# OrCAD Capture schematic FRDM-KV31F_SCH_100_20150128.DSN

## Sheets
1 1. Title Page: title: FRDM-KV31F; rev: X1; company: Freescale Semiconductor; note: SCH-28163 | PDF: SPF-28163; note: 6501 William Cannon Drive West; note: Austin, TX 78735-8598
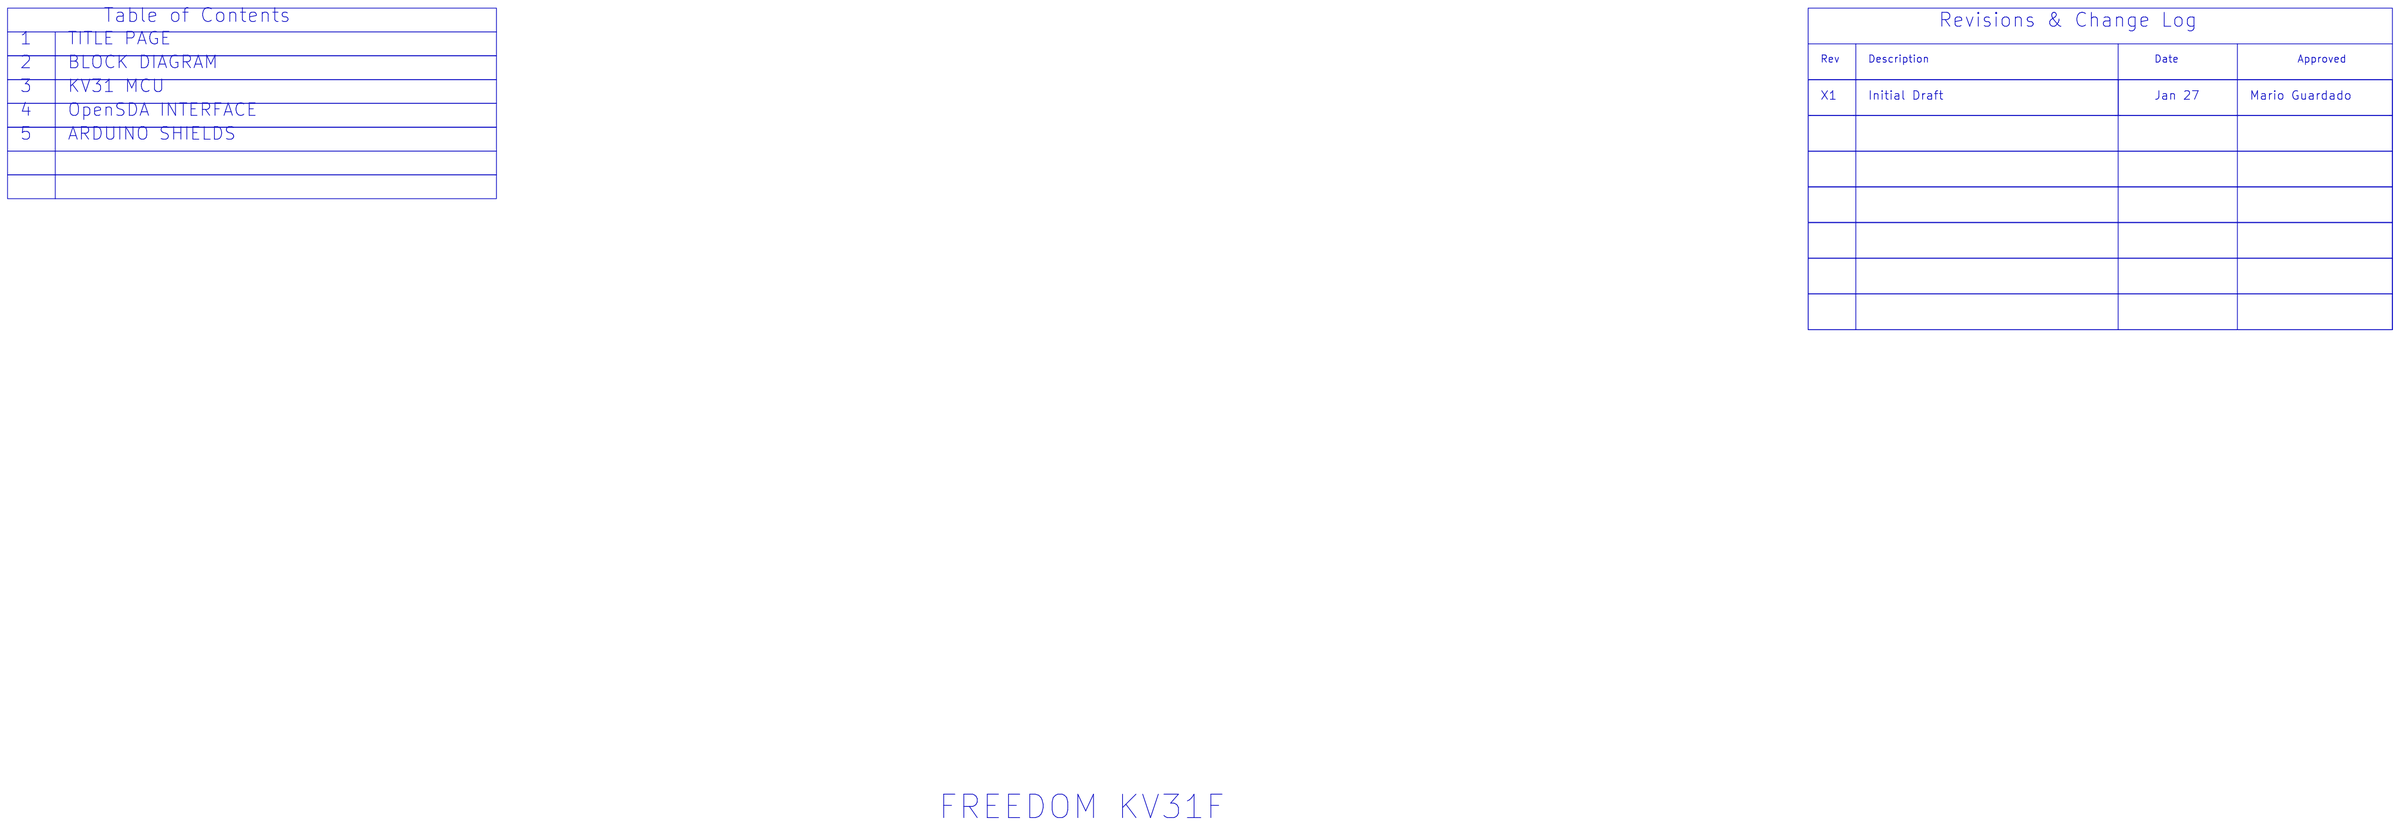
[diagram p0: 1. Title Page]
2 2. Block Diagram
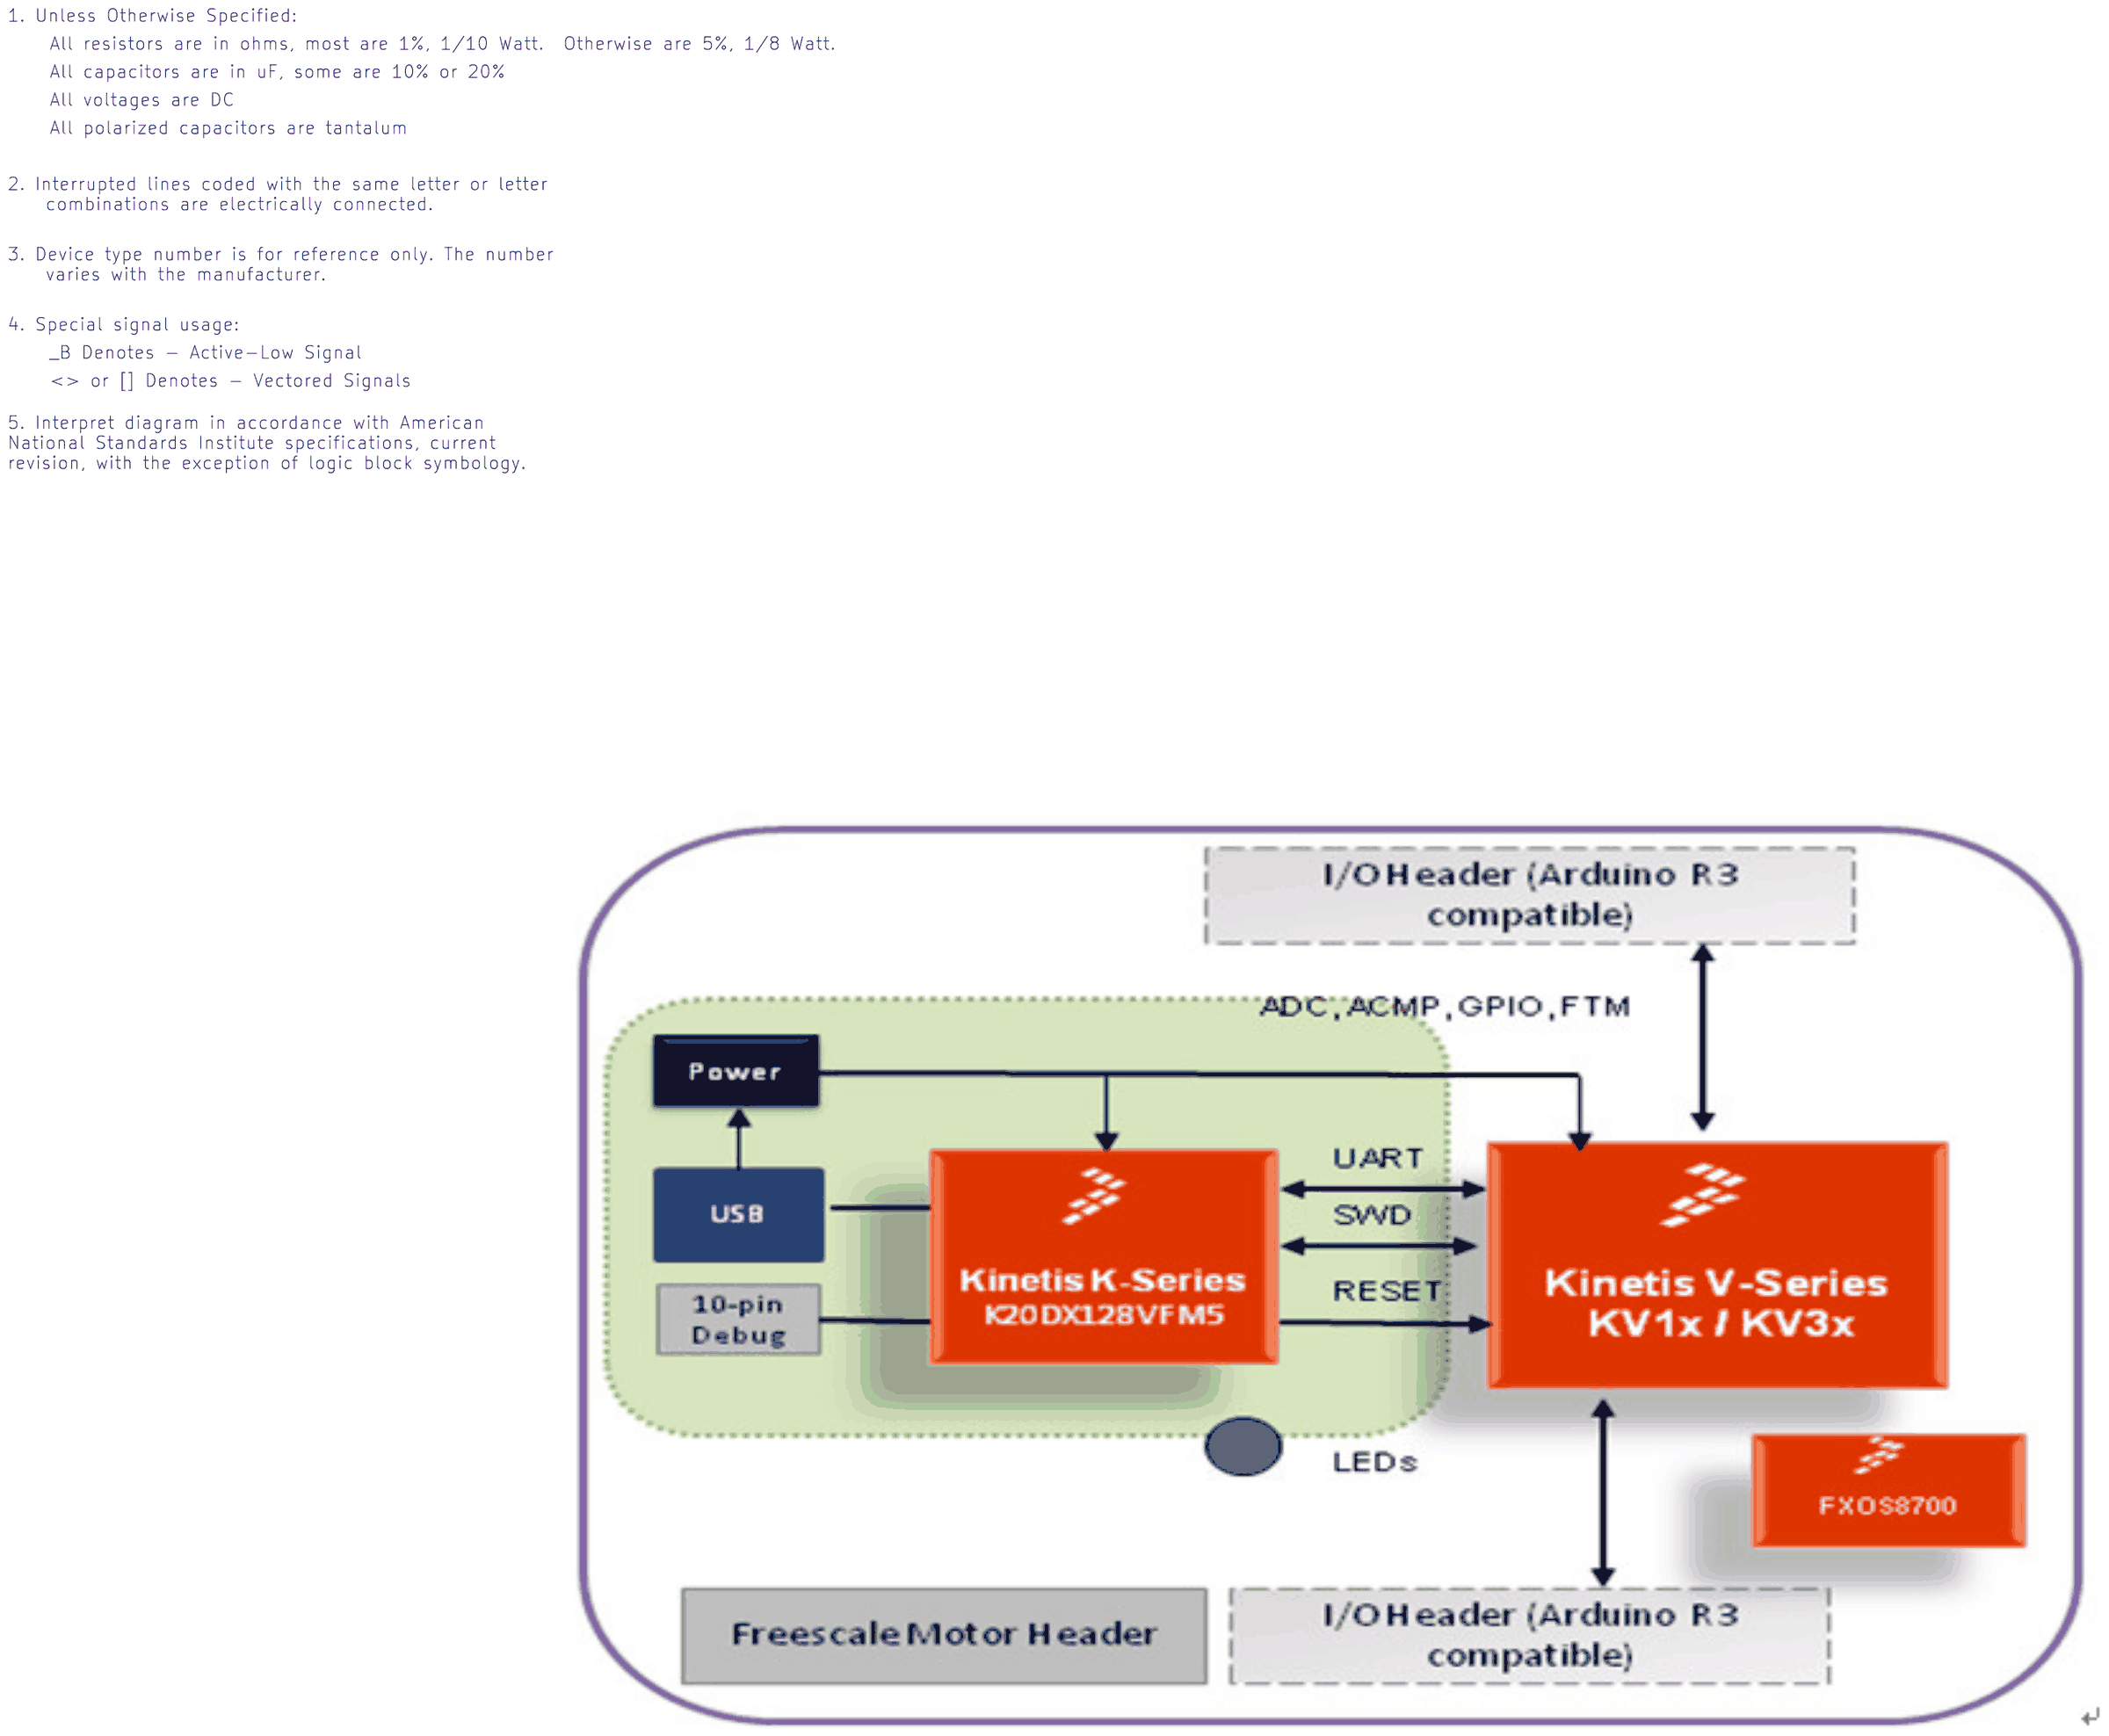
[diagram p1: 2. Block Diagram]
3 3. KV31 MCU: size C
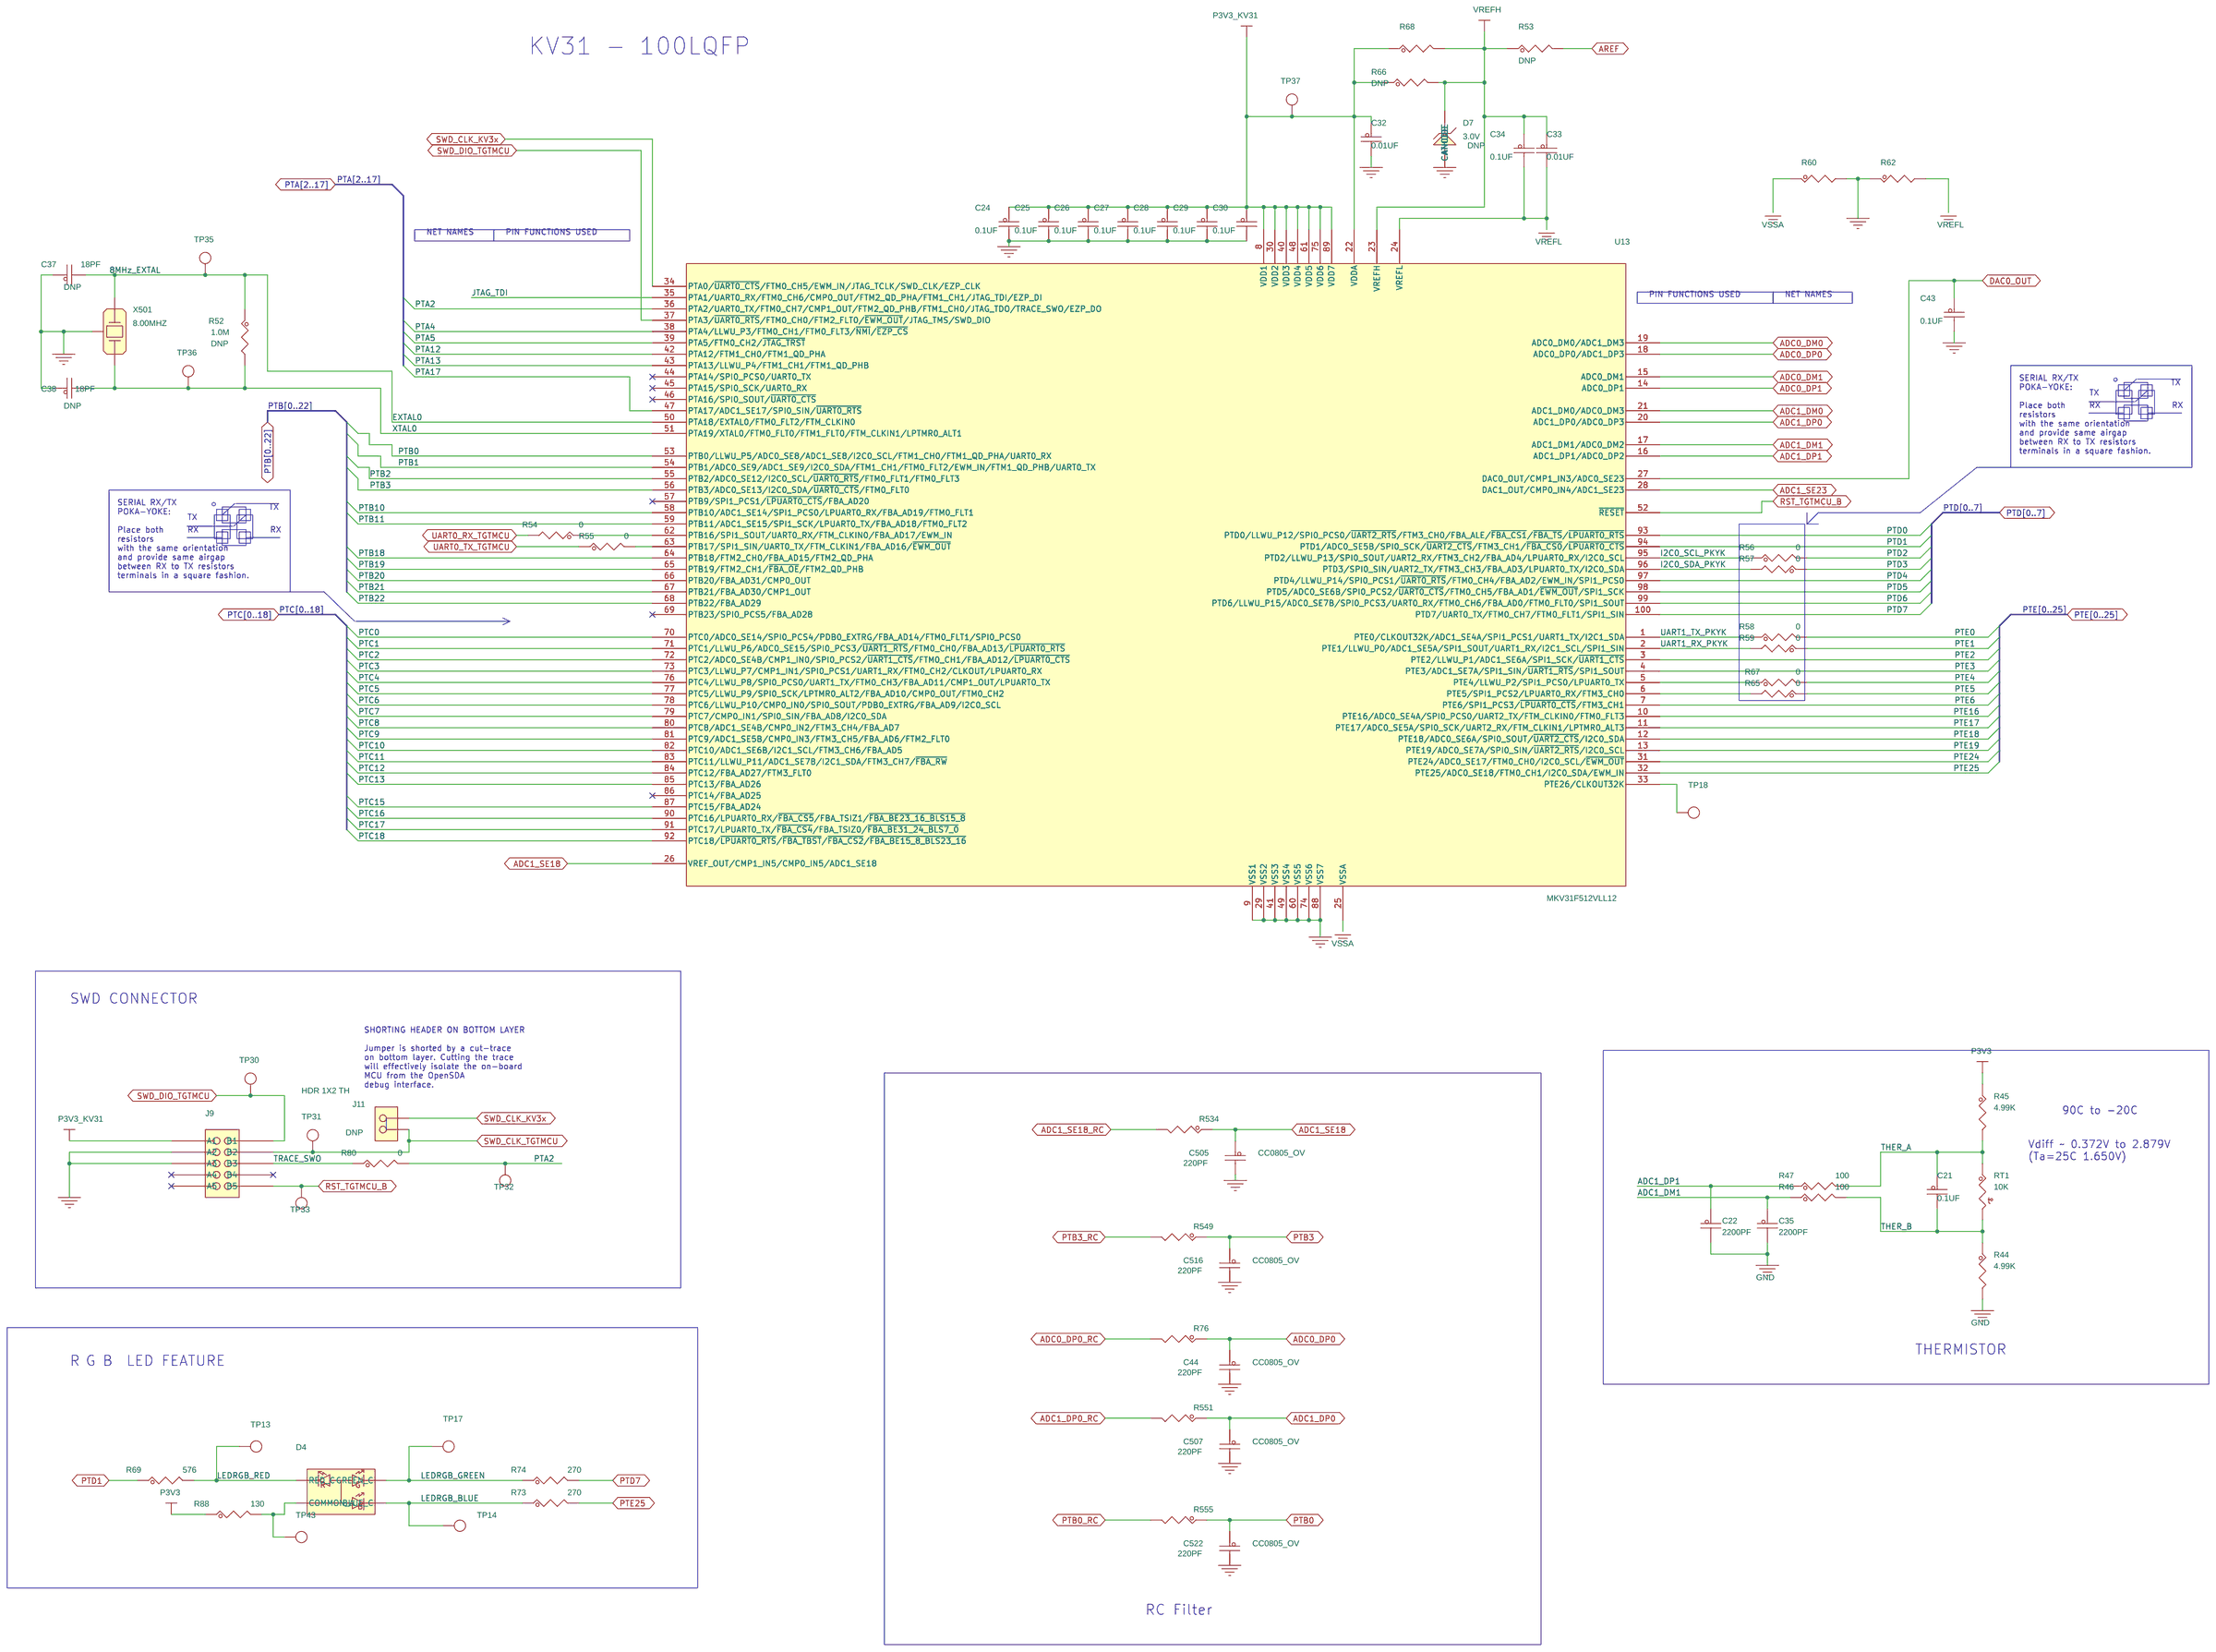
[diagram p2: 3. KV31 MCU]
4 4 OpenSDA interface: size D
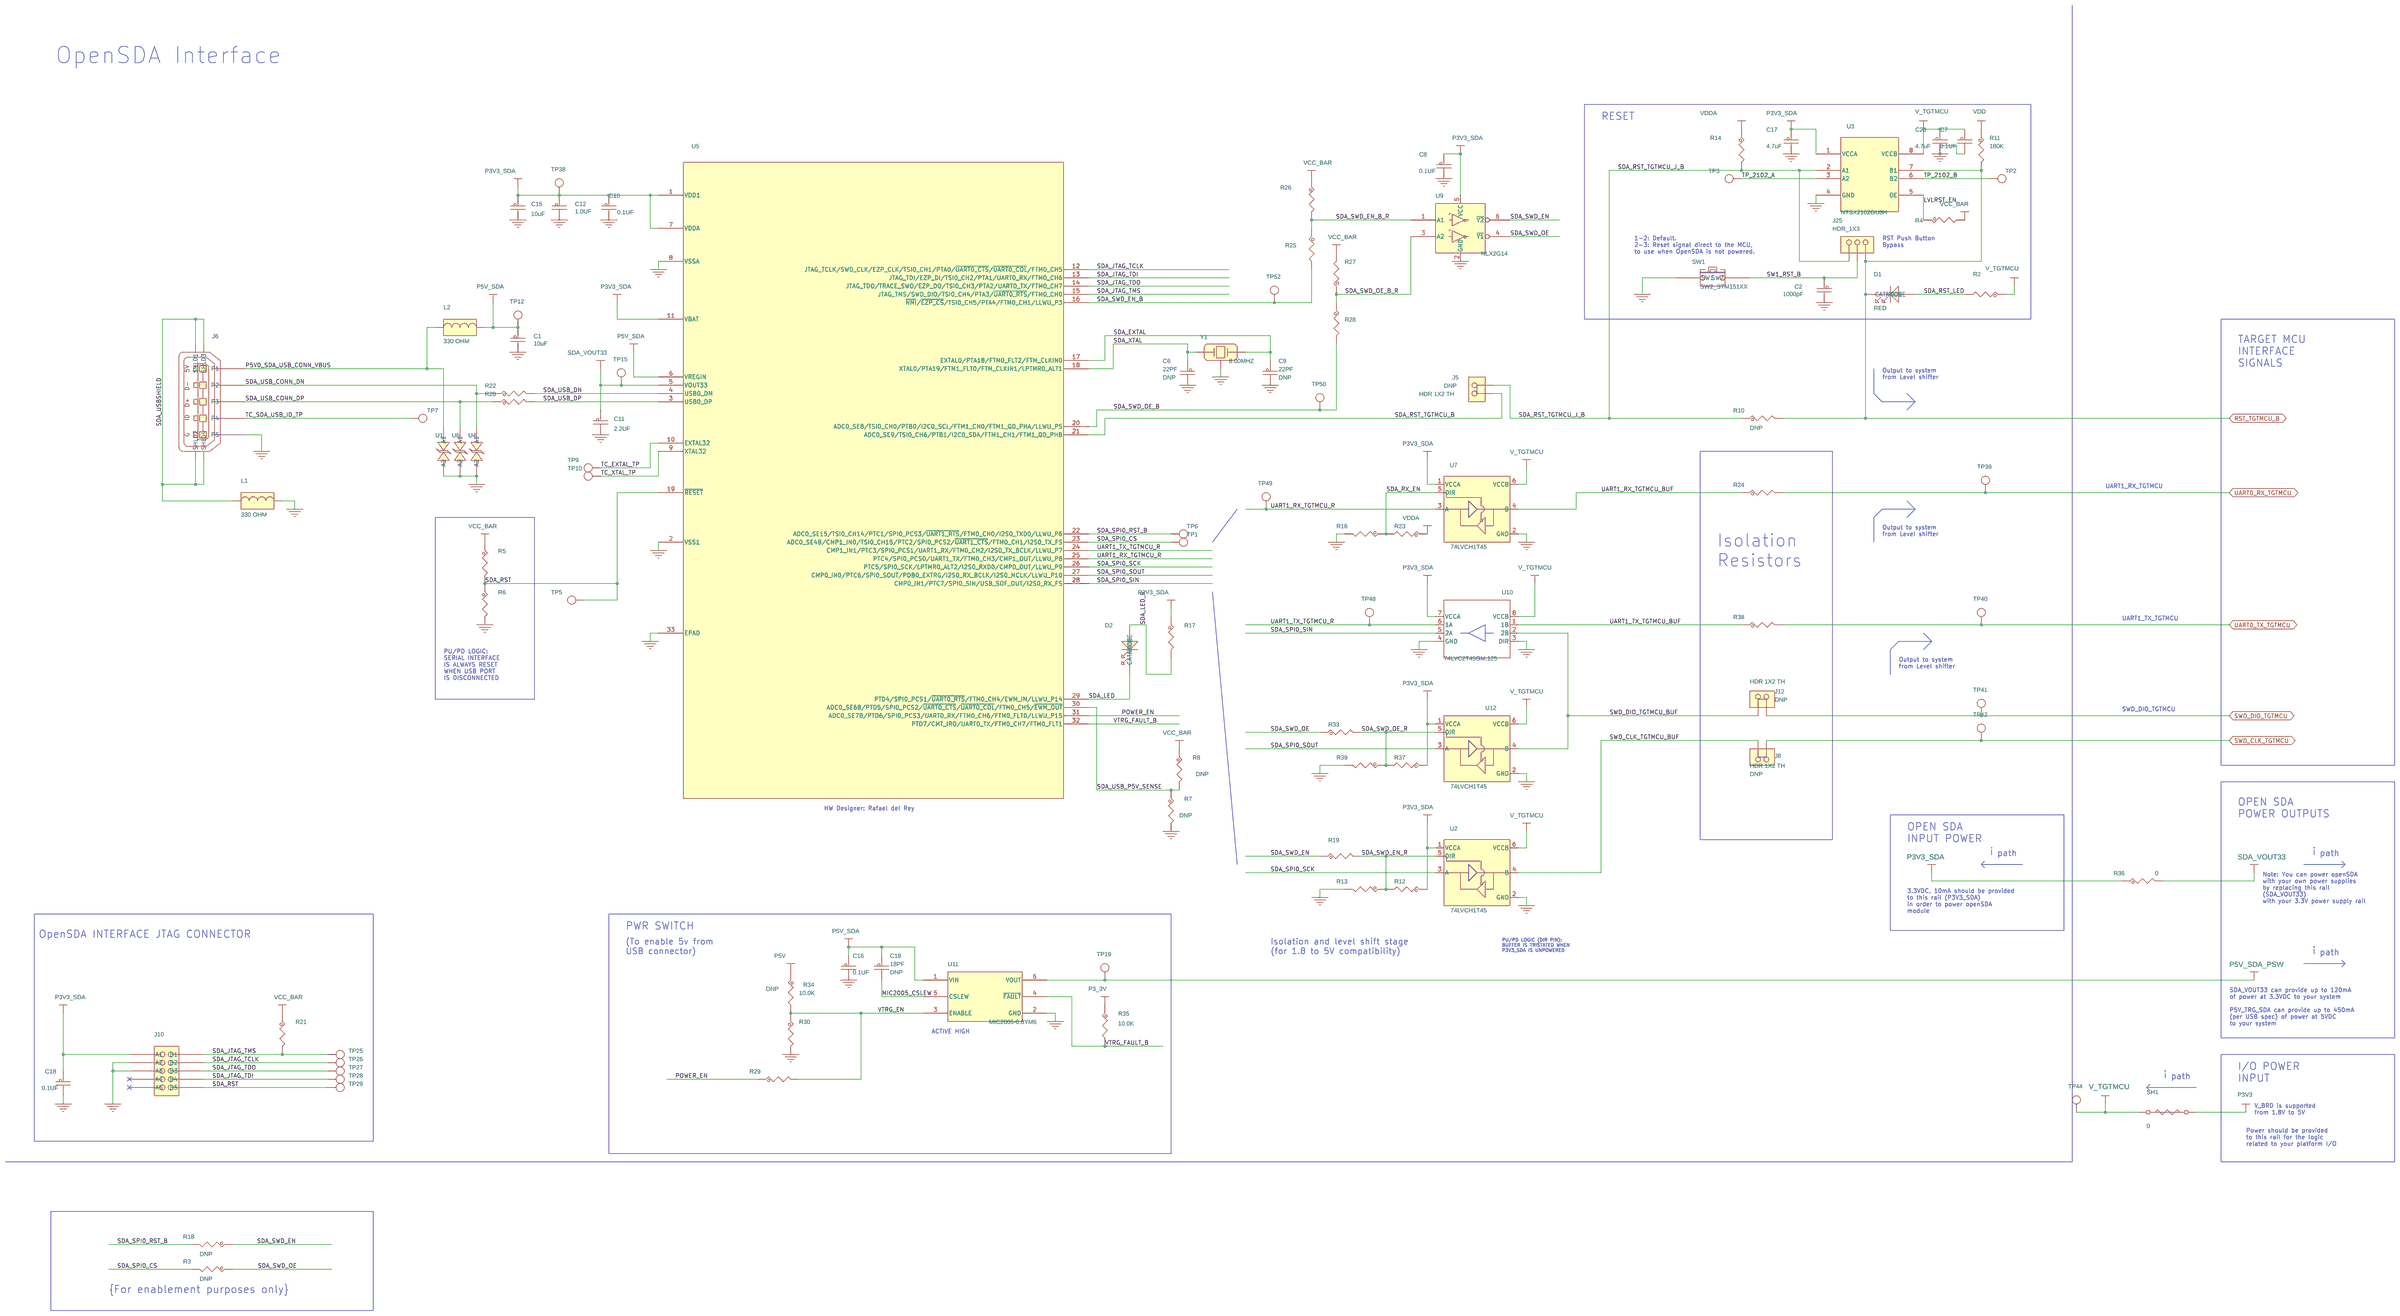
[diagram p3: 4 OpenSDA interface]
5 5. ARDUINO SHIELDS&COMBO SENSOR: size C
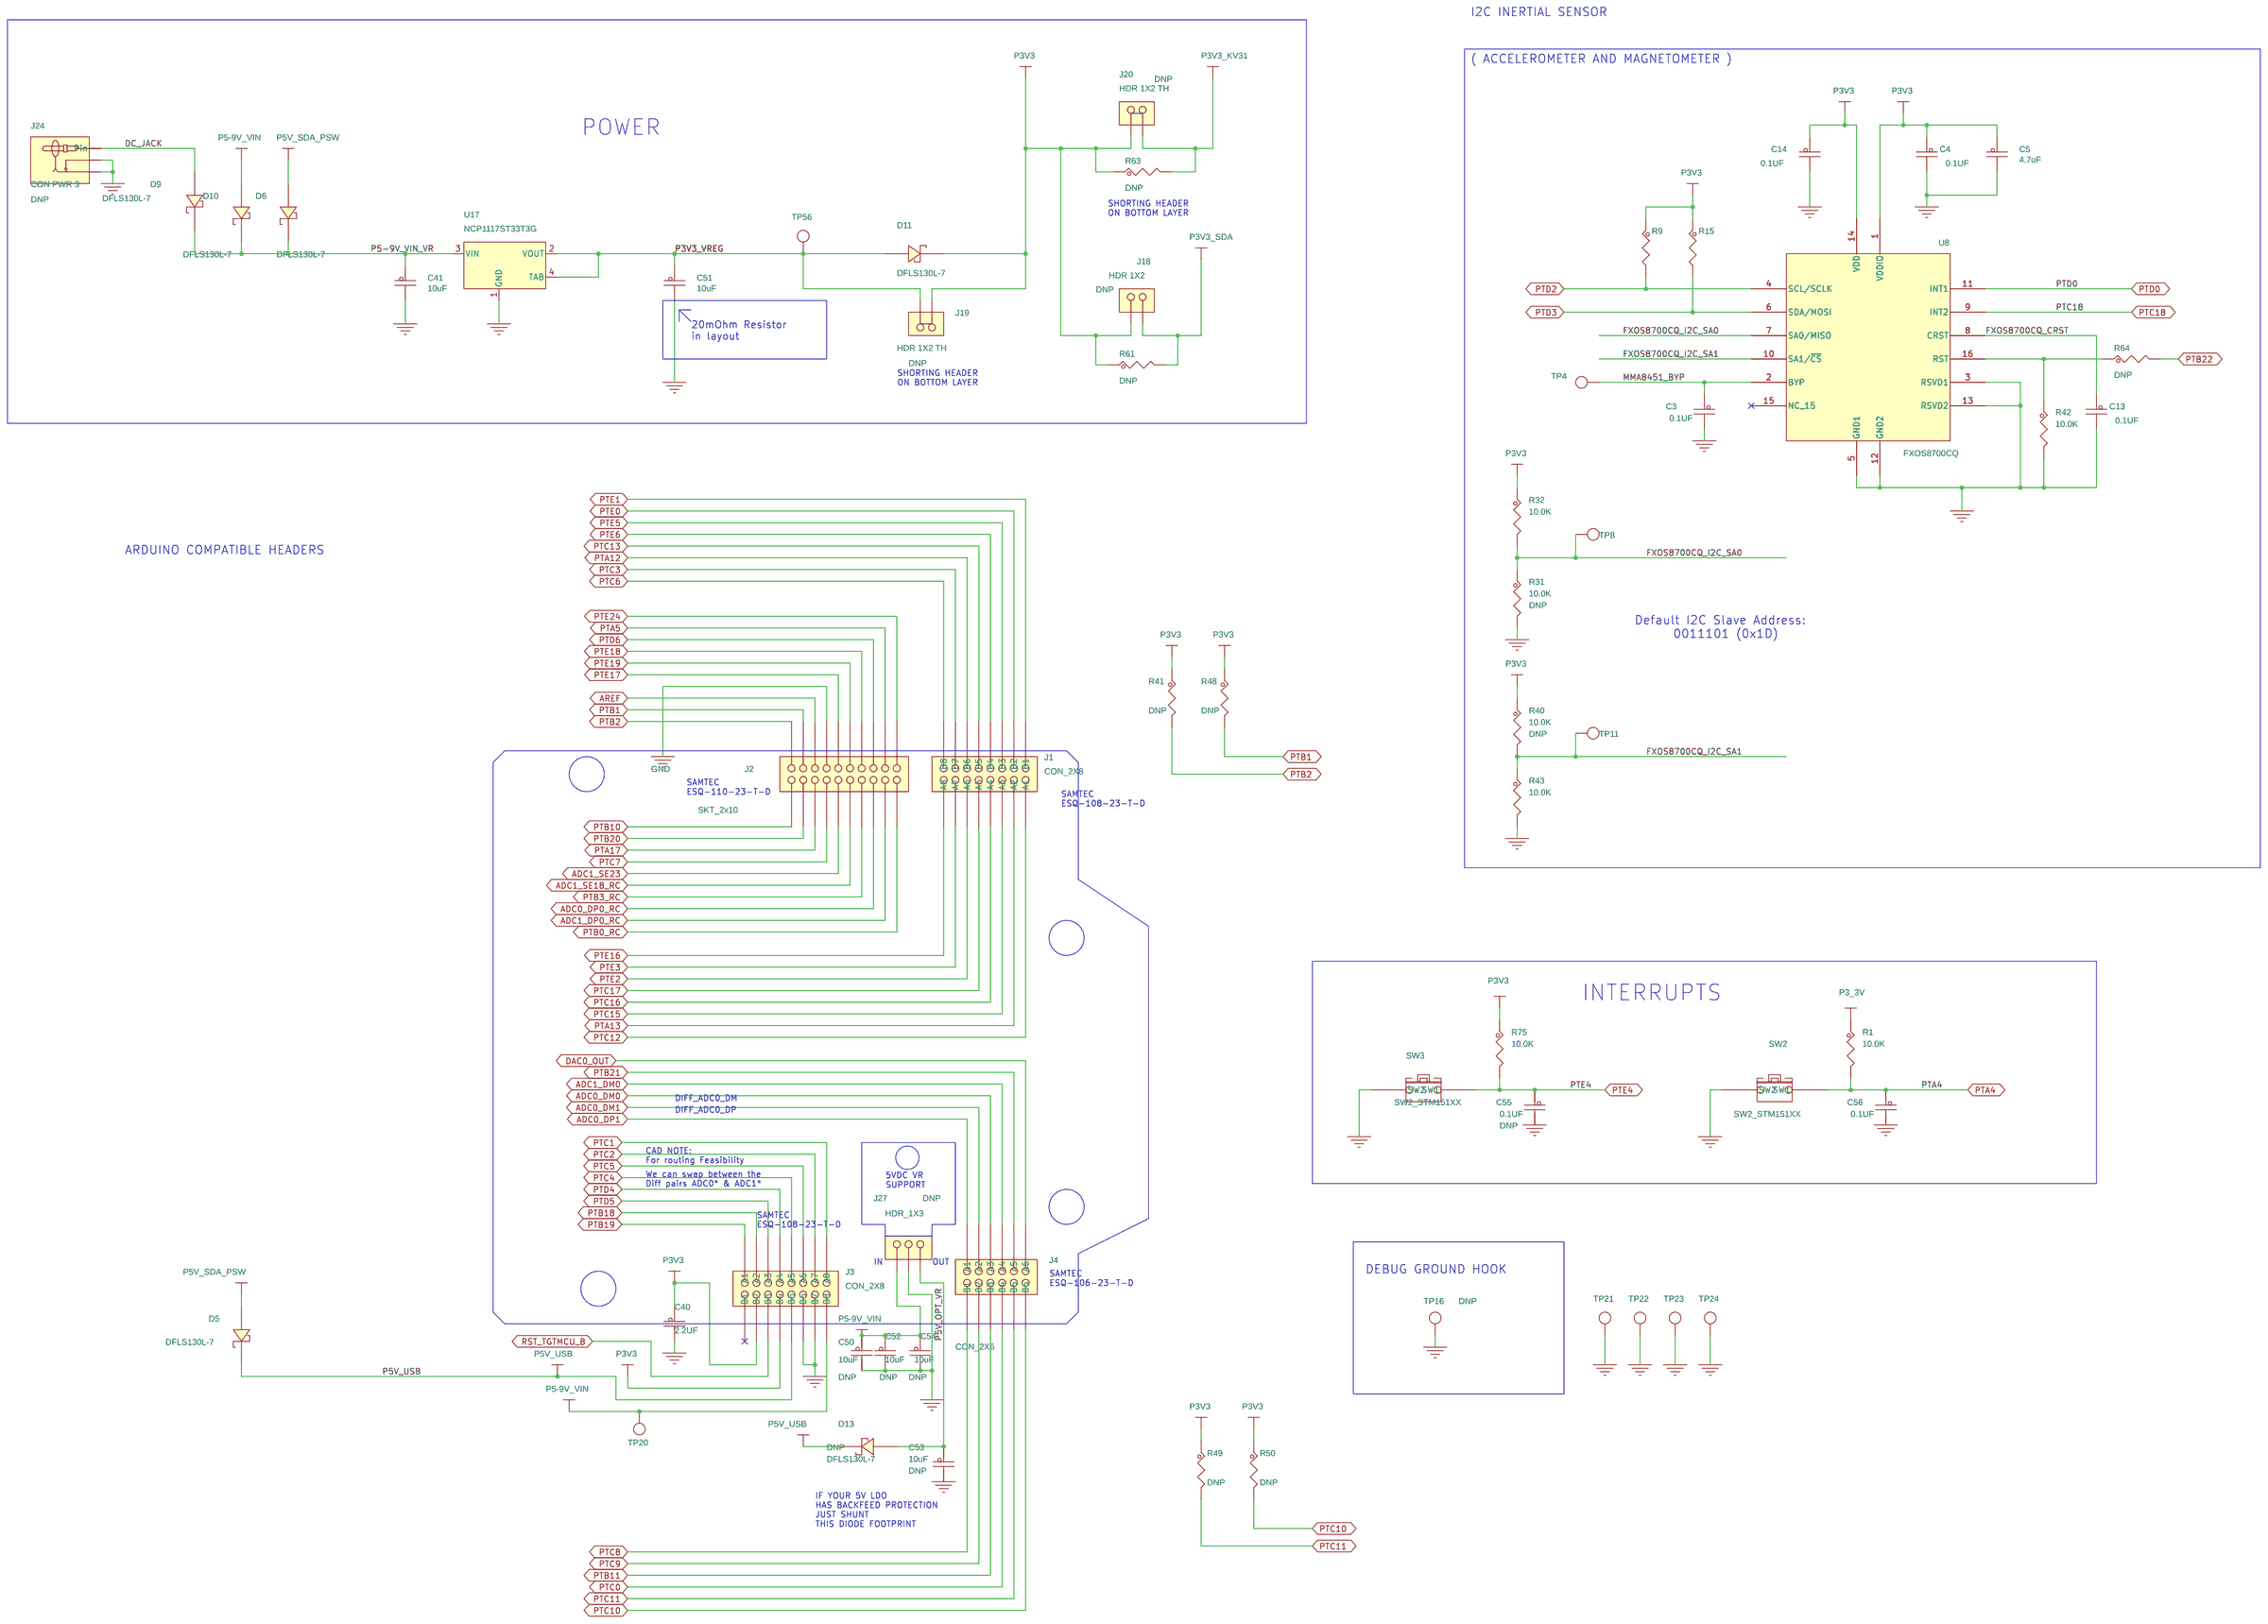
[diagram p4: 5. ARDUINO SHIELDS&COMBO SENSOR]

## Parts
sheet 3. KV31 MCU
C21  0.1UF  [CC0402_25]
C22  2200PF  [CC0402_25]
C24  0.1UF  [CC0402_25]
C25  0.1UF  [CC0402_25]
C26  0.1UF  [CC0402_25]
C27  0.1UF  [CC0402_25]
C28  0.1UF  [CC0402_25]
C29  0.1UF  [CC0402_25]
C30  0.1UF  [CC0402_25]
C32  0.01UF  [CC0402_25]
C33  0.01UF  [CC0402_25]
C34  0.1UF  [CC0402_25]
C35  2200PF  [CC0402_25]
C37  18PF  [CC0603_OV]
C38  18PF  [CC0603_OV]
C43  0.1UF  [CC0402_25]
C44  220PF  [CC0805_OV]
C505  220PF  [CC0805_OV]
C507  220PF  [CC0805_OV]
C516  220PF  [CC0805_OV]
C522  220PF  [CC0805_OV]
D4  CLV1A-FKB-CJ1M1F1BB7R4S3  [led4_3p4x3mm_smt]
D7  3.0V  [sod-323-A]
J9  HDR 2X5  [hdr_5X2_ftsh_th_nsp]
J11  HDR 1X2 TH  [SH_HDR102_BOTTOM]
R44  4.99K  [RC0603_OV]
R45  4.99K  [RC0603_OV]
R46  100  [RC0402_25]
R47  100  [RC0402_25]
R52  1.0M  [RC0603_OV]
R53  0  [RC0402_25]
R54  0  [RC0402_25]
R55  0  [RC0402_25]
R56  0  [RC0402_25]
R57  0  [RC0402_25]
R58  0  [RC0402_25]
R59  0  [RC0402_25]
R60  0  [RC0402_25]
R62  0  [RC0402_25]
R65  0  [RC0402_25]
R66  1K  [RC0603_OV]
R67  0  [RC0402_25]
R68  0  [RC0402_25]
R69  576  [RC0402_25]
R73  270  [RC0402_25]
R74  270  [RC0402_25]
R76  100  [RC0402_25]
R80  0  [RC0402_25]
R88  130  [RC0402_25]
R534  100  [RC0402_25]
R549  100  [RC0402_25]
R551  100  [RC0402_25]
R555  100  [RC0402_25]
RT1  10K  [RC0603_OV]
TP13  TPAD_030  [TPAD_030]
TP14  TPAD_030  [TPAD_030]
TP17  TPAD_030  [TPAD_030]
TP18  TPAD_030  [TPAD_030]
TP30  TPAD_030  [TPAD_030]
TP31  TPAD_030  [TPAD_030]
TP32  TPAD_030  [TPAD_030]
TP33  TPAD_030  [TPAD_030]
TP35  TPAD_030  [TPAD_030]
TP36  TPAD_030  [TPAD_030]
TP37  TPAD_030  [TPAD_030]
TP43  TPAD_030  [TPAD_030]
U13  MKV31F512VLL12  [LQFP100_0P5_14X14]
X501  8.00MHZ  [xtal3_3p35x1p45_sm]
sheet 4 OpenSDA interface
C1  10uF  [CC0402_25]
C2  1000pF  [CC0402_25]
C6  22PF  [CC0402_25]
C7  0.1UF  [CC0402_25]
C8  0.1UF  [CC0402_25]
C9  22PF  [CC0402_25]
C10  0.1UF  [CC0402_25]
C11  2.2UF  [CC0603_OV]
C12  1.0UF  [CC0402_25]
C15  10uF  [CC0603_OV]
C16  0.1UF  [CC0402_25]
C17  4.7uF  [CC0402_25]
C18  0.1UF  [CC0402_25]
C19  18PF  [CC0603_OV]
C23  4.7uF  [CC0402_25]
D1  RED  [LED_0603]
D2  LED GREEN  [LED_0603]
J5  HDR 1X2 TH  [SH_HDR102_BOTTOM]
J6  MICRO USB AB 5  [con5_microusb]
J8  HDR 1X2 TH  [SH_HDR102_BOTTOM]
J10  HDR 2X5  [hdr_5X2_ftsh_th_nsp]
J12  HDR 1X2 TH  [SH_HDR102_BOTTOM]
J25  HDR_1X3  [HDR103]
L1  330 OHM  [ind_1608]
L2  330 OHM  [ind_1608]
R2  100  [RC0402_25]
R3  0  [RC0402_25]
R4  4.7K  [RC0402_25]
R5  4.7K  [RC0402_25]
R6  10.0K  [RC0402_25]
R7  10.0K  [RC0402_25]
R8  4.7K  [RC0402_25]
R10  0  [RC0402_25]
R11  180K  [RC0402_25]
R12  4.7K  [RC0402_25]
R13  10.0K  [RC0402_25]
R14  10.0K  [RC0402_25]
R16  10.0K  [RC0402_25]
R17  220  [RC0603_OV]
R18  0  [RC0402_25]
R19  0  [RC0402_25]
R20  33  [RC0402_25]
R21  10.0K  [RC0402_25]
R22  33  [RC0402_25]
R23  4.7K  [RC0402_25]
R24  0  [RC0402_25]
R25  0  [RC0402_25]
R26  10.0K  [RC0402_25]
R27  10.0K  [RC0402_25]
R28  0  [RC0402_25]
R29  1.0K  [RC0402_25]
R30  15K  [RC0402_25]
R33  0  [RC0402_25]
R34  10.0K  [RC0402_25]
R35  10.0K  [RC0402_25]
R36  0  [RC0603_OV]
R37  4.7K  [RC0402_25]
R38  0  [RC0402_25]
R39  10.0K  [RC0402_25]
SH1  0  [SH0603]
SW1  SW2_STM151XX  [sw2_4x3mm_sm]
TP1  TPAD_030  [TPAD_030]
TP2  TPAD_030  [TPAD_030]
TP3  TPAD_030  [TPAD_030]
TP5  TPAD_030  [TPAD_030]
TP6  TPAD_030  [TPAD_030]
TP7  TPAD_030  [TPAD_030]
TP9  TPAD_030  [TPAD_030]
TP10  TPAD_030  [TPAD_030]
TP12  TPAD_030  [TPAD_030]
TP15  TPAD_030  [TPAD_030]
TP19  TPAD_030  [TPAD_030]
TP25  TPAD_030  [TPAD_030]
TP26  TPAD_030  [TPAD_030]
TP27  TPAD_030  [TPAD_030]
TP28  TPAD_030  [TPAD_030]
TP29  TPAD_030  [TPAD_030]
TP38  TPAD_030  [TPAD_030]
TP39  TPAD_030  [TPAD_030]
TP40  TPAD_030  [TPAD_030]
TP41  TPAD_030  [TPAD_030]
TP42  TPAD_030  [TPAD_030]
TP44  TPAD_030  [TPAD_030]
TP48  TPAD_030  [TPAD_030]
TP49  TPAD_030  [TPAD_030]
TP50  TPAD_030  [TPAD_030]
TP52  TPAD_030  [TPAD_030]
U1  0402ESDA-MLP  [0402_mlp]
U2  74LVCH1T45  [udfn6_1x1p5mm]
U3  NTSX2102GU8H  [xqfn8_1p45x1p25mm]
U4  0402ESDA-MLP  [0402_mlp]
U5  MK20DX128VFM5  [QFN32_S142EP]
U6  0402ESDA-MLP  [0402_mlp]
U7  74LVCH1T45  [udfn6_1x1p5mm]
U9  NLX2G14  [ullga6_1p45x1_0p5mm]
U10  74LVC2T45GM,125  [qfn8_1p6x1p6mm]
U11  MIC2005-0.8YM6  [SOT23-6_a]
U12  74LVCH1T45  [udfn6_1x1p5mm]
Y1  8.00MHZ  [xtal3_3p35x1p45_sm]
sheet 5. ARDUINO SHIELDS&COMBO SENSOR
C3  0.1UF  [CC0402_25]
C4  0.1UF  [CC0402_25]
C5  4.7uF  [CC0603_OV]
C13  0.1UF  [CC0402_25]
C14  0.1UF  [CC0402_25]
C40  2.2UF  [CC0603_OV]
C41  10uF  [CC0603_OV]
C50  10uF  [CC0603_OV]
C51  10uF  [CC0603_OV]
C52  10uF  [CC0603_OV]
C53  10uF  [CC0603_OV]
C54  10uF  [CC0603_OV]
C55  0.1UF  [CC0402_25]
C56  0.1UF  [CC0402_25]
D5  DFLS130L-7  [powerdi-123_3mmx2mm]
D6  DFLS130L-7  [powerdi-123_3mmx2mm]
D9  DFLS130L-7  [powerdi-123_3mmx2mm]
D10  DFLS130L-7  [powerdi-123_3mmx2mm]
D11  DFLS130L-7  [powerdi-123_3mmx2mm]
D13  DFLS130L-7  [powerdi-123_3mmx2mm]
J1  CON_2X8  [HDR208_ESQ_SKT]
J2  SKT_2x10  [hdr210_esq_skt]
J3  CON_2X8  [HDR208_ESQ_SKT]
J4  CON_2X6  [HDR206_ESQ_SKT]
J18  HDR 1X2  [hdr102]
J19  HDR 1X2 TH  [SH_HDR102_BOTTOM]
J20  HDR 1X2 TH  [SH_HDR102_BOTTOM]
J24  CON PWR 3  [con_jack_pj1_022_th-ra]
J27  HDR_1X3  [HDR103]
R1  10.0K  [RC0402_25]
R9  4.7K  [RC0402_25]
R15  4.7K  [RC0402_25]
R31  10.0K  [RC0402_25]
R32  10.0K  [RC0402_25]
R40  10.0K  [RC0402_25]
R41  4.7K  [RC0402_25]
R42  10.0K  [RC0402_25]
R43  10.0K  [RC0402_25]
R48  4.7K  [RC0402_25]
R49  4.7K  [RC0402_25]
R50  4.7K  [RC0402_25]
R61  0  [RC0402_25]
R63  10  [RC0402_25]
R64  0  [RC0402_25]
R75  10.0K  [RC0402_25]
SW2  SW2_STM151XX  [sw2_4x3mm_sm]
SW3  SW2_STM151XX  [sw2_4x3mm_sm]
TP4  TPAD_030  [TPAD_030]
TP8  TPAD_030  [TPAD_030]
TP11  TPAD_030  [TPAD_030]
TP16  TEST POINT WHITE  [TEST_LOOP]
TP20  TPAD_030  [TPAD_030]
TP21  TPAD_030  [TPAD_030]
TP22  TPAD_030  [TPAD_030]
TP23  TPAD_030  [TPAD_030]
TP24  TPAD_030  [TPAD_030]
TP56  TPAD_030  [TPAD_030]
U8  FXOS8700CQ  [qfn5x3_0p5_3x3]
U17  NCP1117ST33T3G  [sot223]

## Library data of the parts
C21 = CAP_NP: CAP CER 0.1UF 10V 10% X5R 0402; AGILE_PN: 150-75634; CAD_APPROVED: Yes; FPLIST: CC0402_25,CC0402_HD,0402_CC; HEIGHT: 0.64MM; MFG_NAME01: KEMET; MFG_PN01: C0402C104K8PAC; ROHS: Yes; Tolerance: 10%; VOLTAGE: 10V
C22 C35 = CAP_NP: CAP CER 2200PF 50V 10%  X7R 0402; AGILE_PN: 150-75600; CAD_APPROVED: Yes; FPLIST: CC0402_25,CC0402_HD,0402_CC; HEIGHT: 0.55MM; MFG_NAME01: MURATA; MFG_PN01: GRM155R71H222KA01D; ROHS: Yes; Tolerance: 10%; VOLTAGE: 50V
C24-C30 C34 C43 = CAP_NP: CAP CER 0.1UF 10V 10% X5R 0402; AGILE_PN: 150-75634; CAD_APPROVED: Yes; FPLIST: CC0402_25,CC0402_HD,0402_CC; HEIGHT: 0.64MM; MFG_NAME01: KEMET; MFG_PN01: C0402C104K8PAC; ROHS: Yes; TOL: 10%; Tolerance: 10%; VOLTAGE: 10V
C32 C33 = CAP_NP: CAP CER 0.01UF 16V 20% X7R 0402; AGILE_PN: 150-30082; CAD_APPROVED: Yes; FPLIST: CC0402_25,CC0402_HD,0402_CC; HEIGHT: 0.56MM; MFG_NAME01: AVX; MFG_PN01: 0402YC103MAT2A; ROHS: Yes; TOL: 20%; Tolerance: 20%; VOLTAGE: 16V
C37 C38 = CAP_NP: CAP CER 18PF 50V 5% C0G 0603; AGILE_PN: 150-75116; ASSY_OPT: DNP; CAD_APPROVED: Yes; FPLIST: CC0603_OV,CC0603,0603_CC; HEIGHT: 0.90MM; MFG_NAME01: YAGEO AMERICA; MFG_PN01: CC0603JRNPO9BN180; ROHS: Yes; TOL: 5%; Tolerance: 5%; VOLTAGE: 50V
C44 C505 C507 C516 C522 = CAP_NP: CAP CER 220PF 50V 10% X7R 0805; AGILE_PN: 150-75217; CAD_APPROVED: YES; FPLIST: CC0805_OV,CC0805,0805_CC; HEIGHT: 1.4732MM; MFG_NAME01: VENKEL COMPANY; MFG_PN01: C0805X7R500-221KNE; ROHS: Yes; Tolerance: 10%; VOLTAGE: 50V
D4 = CLV1A_LED_4P: LED RED BL GRN SGL 50/25/25mA SMT; AGILE_PN: 370-76567; CAD_APPROVED: Yes; HEIGHT: 2.1MM; MFG_NAME01: CREE, INC; ROHS: Yes
D7 = ZDIODE: DIODE ZNR -- 3V 200MW SOD323; AGILE_PN: 480-78396; ASSY_OPT: DNP; CAD_APPROVED: Yes; HEIGHT: 1.1MM; MFG_NAME01: ON SEMICONDUCTOR; MFG_PN01: MM3Z3V0T1G; ROHS: Yes
J9 J10 = CONN_HDR_5X2: HDR 2X5 TH 50MIL CTR 167H AU 91L; AGILE_PN: 210-80192; CAD_APPROVED: Yes; FPLIST: hdr_5X2_ftsh_th,hdr_5X2_ftsh_th_nsp; HEIGHT: 4.25MM; MFG_NAME01: ANYTRONIC CORPORATION LIMITED; MFG_PN01: 0922S0205011N6T-2LF; ROHS: Yes
J5 J8 J11 J12 J19 J20 = CONN_HDR_2X1: HDR 1X2 TH 100MIL SP 339H AU 98L; AGILE_PN: 210-75439; ASSY_OPT: DNP; CAD_APPROVED: YES; FPLIST: HDR102,SH_HDR102_BOTTOM; HEIGHT: 8.71 MM; MFG_NAME01: SAMTEC; MFG_PN01: TSW-102-07-G-S; PRIORITY_PN: 028-00556; ROHS: Yes
R44 R45 = RES: RES MF 4.99K 1/10W 1% 0603; AGILE_PN: 470-75771; CAD_APPROVED: Yes; FPLIST: RC0603_OV,RC0603,0603_CC; MFG_NAME01: KOA SPEER; MFG_PN01: RK73H1JTTD4991F; ROHS: Yes; Tolerance: 1%
R46 R47 = RES: RES MF 100 OHM 1/16W 1% 0402; AGILE_PN: 470-30454; CAD_APPROVED: Yes; FPLIST: RC0402_25,RC0402_HD,0402_CC; MFG_NAME01: THYE MING TECH CO LTD; MFG_PN01: CR-02FL6--100R; ROHS: Yes; Tolerance: 1%
R52 = RES: RES MF 1.0M 1/10W 5% 0603; AGILE_PN: 470-75846; ASSY_OPT: DNP; CAD_APPROVED: Yes; FPLIST: RC0603_OV,RC0603,0603_CC; HEIGHT: 0.55MM; MFG_NAME01: BOURNS; MFG_PN01: CR0603-JW-105ELF; ROHS: Yes; TOL: 5%; Tolerance: 5%
R53 R61 R63 R64 = RES: RES MF ZERO OHM 1/16W 5% 0402; AGILE_PN: 470-75394; ASSY_OPT: DNP; CAD_APPROVED: Yes; FPLIST: RC0603_OV,RC0603,R603-X2,0603_CC; MFG_NAME01: ROHM; MFG_PN01: MCR01MZPJ000; PRIORITY_PN: 006-00559; ROHS: Yes; SIGNAL_MODEL: DEFAULT_RESISTOR_0.001OHM_2_1; Tolerance: 5%; VOLTAGE: 1/16W
R54-R59 R65 R67 = RES: RES MF ZERO OHM 1/16W 5% 0402; AGILE_PN: 470-75394; CAD_APPROVED: Yes; FPLIST: RC0402_25,RC0402_HD,RC0402_X2,0402_CC; HEIGHT: 0.6MM; MFG_NAME01: ROHM; MFG_PN01: MCR01MZPJ000; ROHS: Yes; TOL: 1%; Tolerance: 5%
R19 R25 R28 R33 R60 R62 R80 = RES: RES MF ZERO OHM 1/16W 5% 0402; AGILE_PN: 470-75394; CAD_APPROVED: Yes; FPLIST: RC0402_25,RC0402_HD,RC0402_X2,0402_CC; MFG_NAME01: ROHM; MFG_PN01: MCR01MZPJ000; PRIORITY_PN: 006-00559; ROHS: Yes; SIGNAL_MODEL: DEFAULT_RESISTOR_0.001OHM_2_1; Tolerance: 5%; VOLTAGE: 1/16W
R66 = RES: RES MF 1.0K 1/10W 5% 0603; AGILE_PN: 470-75412; ASSY_OPT: DNP; CAD_APPROVED: YES; FPLIST: RC0603_OV,RC0603,0603_CC; MFG_NAME01: VENKEL COMPANY; MFG_PN01: CR0603-10W-102JT; ROHS: Yes; SIGNAL_MODEL: DEFAULT_RESISTOR_1000.000000OHM_2_1; Tolerance: 5%
R68 = RES: RES MF ZERO OHM 1/16W 5% 0402; AGILE_PN: 470-75394; CAD_APPROVED: Yes; FPLIST: RC0603_OV,RC0603,R603-X2,0603_CC; MFG_NAME01: ROHM; MFG_PN01: MCR01MZPJ000; PRIORITY_PN: 006-00559; ROHS: Yes; SIGNAL_MODEL: DEFAULT_RESISTOR_0.001OHM_2_1; Tolerance: 5%; VOLTAGE: 1/16W
R69 = RES: RES MF 576 OHM 1/16W 1% 0402; AGILE_PN: 470-30813; CAD_APPROVED: Yes; FPLIST: RC0402_25,RC0402_HD,0402_CC; MFG_NAME01: KOA SPEER; MFG_PN01: RK73H1ETTP5760F; ROHS: Yes; Tolerance: 1%
R73 R74 = RES: RES MF 270 OHM 1/16W 5% 0402; AGILE_PN: 470-30332; CAD_APPROVED: Yes; FPLIST: RC0402_25,RC0402_HD,0402_CC; MFG_NAME01: VISHAY INTERTECHNOLOGY; MFG_PN01: CRCW0402270RJNED; ROHS: Yes; Tolerance: 5%
R76 R534 R549 R551 R555 = RES: RES MF 100 OHM 1/16W 5% 0402; AGILE_PN: 470-75591; CAD_APPROVED: Yes; FPLIST: RC0402_25,RC0402_HD,RC0402_X2,0402_CC; HEIGHT: 0.55 MM; MFG_NAME01: VENKEL COMPANY; MFG_PN01: CR040216W101JT; ROHS: Yes; TOL: 1%; Tolerance: 5%
R88 = RES: RES MF 130 OHM 1/16W 1% 0402; AGILE_PN: 470-30515; CAD_APPROVED: Yes; FPLIST: RC0402_25,RC0402_HD,0402_CC; MFG_NAME01: VISHAY INTERTECHNOLOGY; MFG_PN01: CRCW0402130RFKED; ROHS: Yes; Tolerance: 1%
RT1 = THERMISTOR: THERMISTOR 10K 1/10W 1% 0603; AGILE_PN: 470-80022; CAD_APPROVED: Yes; FPLIST: RC0603_OV,RC0603,0603_CC; MFG_NAME01: MuRata; MFG_PN01: NCP18XH103F03RB; ROHS: Yes; Tolerance: 1%
TP1-TP15 TP17-TP33 TP35-TP44 TP48-TP50 TP52 TP56 = TestLoop: TEST POINT PAD 30MIL DIA SMT, NO PART TO ORDER; AGILE_PN: 211-76642; CAD_APPROVED: Yes; HEIGHT: 0.1MM; MFG_NAME01: NOTACOMPONENT; MFG_PN01: NOTACOMPONENT; ROHS: Yes
U13 = MKV10FN_LQFP_100P: IC MCU 32BIT 512KB FLASH 96KB RAM 1.71-3.6V 120MHZ LQFP100; AGILE_PN: TMP-WF-19688; CAD_APPROVED: Yes; HEIGHT: 1.7MM; MFG_NAME01: FREESCALE SEMICONDUCTOR; PRE_APN: 344-01918; ROHS: Yes
X501 = XTAL_CS: XTAL 8.00MHZ RSN CERAMIC -- SMT; AGILE_PN: 230-77664; CAD_APPROVED: Yes; HEIGHT: 0.8MM; MFG_NAME01: MURATA; MFG_PN01: CSTCE8M00G55-R0; ROHS: Yes
C1 = CAP_NP: CAP CER 10uF 10V 20% X5R 0402; AGILE_PN: 150-79255; CAD_APPROVED: Yes; FPLIST: C0402_25,CC0402_HD,0402_CC; HEIGHT: 0.7MM; MFG_NAME01: SAMSUNG; MFG_PN01: CL05A106MP5NUNC; PRIORITY_PN: 021-00242; ROHS: Yes; SIGNAL_MODEL: DEFAULT_CAPACITOR_1e+06pF_2_1; Tolerance: 20%; VOLTAGE: 10V
C2 = CAP_NP: CAP CER 1000PF 50V 5% C0G 0402; AGILE_PN: 150-76334; CAD_APPROVED: Yes; FPLIST: CC0402_25,CC0402_HD,0402_CC; HEIGHT: 0.55MM; MFG_NAME01: MURATA; MFG_PN01: GRM1555C1H102JA01D; ROHS: Yes; Tolerance: 5%; VOLTAGE: 50V
C6 C9 = CAP_NP: CAP CER 22PF 50V 5% C0G 0402; AGILE_PN: 150-75266; ASSY_OPT: DNP; CAD_APPROVED: Yes; FPLIST: CC0402_25,CC0402_HD,0402_CC; HEIGHT: 0.635MM; MFG_NAME01: AVX; MFG_PN01: 04025A220JAT2A; PRIORITY_PN: 021-00234; ROHS: Yes; SIGNAL_MODEL: DEFAULT_CAPACITOR_22.000000pF_2_1; Tolerance: 5%; VOLTAGE: 50V
C7 C8 C10 C16 C18 = CAP_NP: CAP CER 0.1UF 10V 10% X5R 0402; AGILE_PN: 150-75634; CAD_APPROVED: Yes; FPLIST: CC0402_25,CC0402_HD,0402_CC; HEIGHT: 0.64MM; MFG_NAME01: KEMET; MFG_PN01: C0402C104K8PAC; PRIORITY_PN: 021-00169; ROHS: Yes; SIGNAL_MODEL: DEFAULT_CAPACITOR_100000pF_2_1; TOL: 10%; Tolerance: 10%; VOLTAGE: 10V
C11 C40 = CAP_NP: CAP CER 2.2UF 10V 10% X7R 0603; AGILE_PN: 150-78564; CAD_APPROVED: Yes; FPLIST: CC0603_OV,CC0603,0603_CC; HEIGHT: 1.25MM; MFG_NAME01: TAIYO YUDEN; MFG_PN01: LMK107B7225KA-T; ROHS: Yes; SIGNAL_MODEL: DEFAULT_CAPACITOR_2.2e+06pF_2_1; Tolerance: 10%; VOLTAGE: 10V
C12 = CAP_NP: CAP CER 1.0UF 10V 10% X5R 0402; AGILE_PN: 150-75772; CAD_APPROVED: Yes; FPLIST: CC0402_25,CC0402_HD,0402_CC; HEIGHT: 0.6MM; MFG_NAME01: YAGEO AMERICA; MFG_PN01: CC0402KRX5R6BB105; PRIORITY_PN: 021-00242; ROHS: Yes; SIGNAL_MODEL: DEFAULT_CAPACITOR_1e+06pF_2_1; VOLTAGE: 10V
C15 = CAP_NP: CAP CER 10uF 16V 20% X5R 0603; AGILE_PN: 150-79092; CAD_APPROVED: Yes; FPLIST: CC0603_OV,CC0603,0603_CC; HEIGHT: 1mm; MFG_NAME01: TAIYO YUDEN; MFG_PN01: EMK107BBJ106MA-T; ROHS: Yes; SIGNAL_MODEL: DEFAULT_CAPACITOR_1e+07pF_2_1; TOL: 10%; Tolerance: 20%; VOLTAGE: 16V
C17 C23 = CAP_NP: CAP CER 4.7UF 6.3V 20% X5R 0402; AGILE_PN: 150-78463; CAD_APPROVED: Yes; FPLIST: CC0402_25,CC0402_HD,0402_CC; HEIGHT: 0.65MM; MFG_NAME01: VENKEL COMPANY; MFG_PN01: C0402X5R6R3-475MNP; PRIORITY_PN: 021-00169; ROHS: Yes; SIGNAL_MODEL: DEFAULT_CAPACITOR_4.7e+06pF_2_1; TOL: 10%; Tolerance: 20%; VOLTAGE: 6.3V
C19 = CAP_NP: CAP CER 18PF 50V 5% C0G 0603; AGILE_PN: 150-75116; ASSY_OPT: DNP; CAD_APPROVED: Yes; FPLIST: CC0603_OV,CC0603,0603_CC; HEIGHT: 0.90MM; MFG_NAME01: YAGEO AMERICA; MFG_PN01: CC0603JRNPO9BN180; PRIORITY_PN: 021-00320; ROHS: Yes; SIGNAL_MODEL: DEFAULT_CAPACITOR_18.000000pF_2_1; TOL: 5%; Tolerance: 5%; VOLTAGE: 50V
D1 = LED: LED ULTRA BRIGHT RED SGL 30MA 0603; AGILE_PN: 370-75079; CAD_APPROVED: Yes; HEIGHT: 0.9MM; MFG_NAME01: LITE ON; MFG_PN01: LTST-C190KRKT; ROHS: Yes
D2 = LED: LED GRN SGL 20MA 0603; AGILE_PN: 370-76565; CAD_APPROVED: Yes; HEIGHT: 0.67MM; MFG_NAME01: osram; MFG_PN01: LG L29K-G2J1-24-Z; ROHS: Yes
J6 = USB_MINI_AB_RECEPTACLE: CON 1X5 USB_MICRO_AB_RECEPTACLE RA SMT 0.65MM SP 105H AU; AGILE_PN: 211-78722; CAD_APPROVED: Yes; HEIGHT: 2.65MM; MFG_NAME01: Molex; MFG_PN01: 47589-0001; ROHS: Yes
J25 = CONN_HDR_3X1: HDR 1X3 TH 100MIL SP 330H AU 98L; AGILE_PN: 210-75442; CAD_APPROVED: Yes; HEIGHT: 8.38 MM; MFG_NAME01: SAMTEC; MFG_PN01: HTSW-103-07-S-S; PRIORITY_PN: 028-00700; ROHS: Yes
L1 L2 = BEAD: IND FER BEAD 330OHM@100MHZ 1.7A 0603; AGILE_PN: 180-78156; CAD_APPROVED: Yes; FPLIST: ind_1608,0603_CC; HEIGHT: 0.95MM; MFG_NAME01: TDK; MFG_PN01: MPZ1608S331A; PART_TYPE: FERRITE\BEAD; ROHS: Yes; Tolerance: 25%
R2 = RES: RES MF 100 OHM 1/16W 5% 0402; AGILE_PN: 470-75591; CAD_APPROVED: Yes; FPLIST: RC0402_25,RC0402_HD,RC0402_X2,0402_CC; HEIGHT: 0.55 MM; MFG_NAME01: VENKEL COMPANY; MFG_PN01: CR040216W101JT; ROHS: Yes; SIGNAL_MODEL: DEFAULT_RESISTOR_100.000000OHM_2_1; TOL: 1%; Tolerance: 5%
R3 R18 = RES: RES MF ZERO OHM 1/16W 5% 0402; AGILE_PN: 470-75394; ASSY_OPT: DNP; CAD_APPROVED: Yes; FPLIST: RC0402_25,RC0402_HD,RC0402_X2,0402_CC; MFG_NAME01: ROHM; MFG_PN01: MCR01MZPJ000; PRIORITY_PN: 006-00559; ROHS: Yes; SIGNAL_MODEL: DEFAULT_RESISTOR_0.001OHM_2_1; Tolerance: 5%; VOLTAGE: 1/16W
R4 R5 R9 R12 R15 R23 R37 = RES: RES MF 4.7K 1/16W 5% 0402; AGILE_PN: 470-75626; CAD_APPROVED: Yes; FPLIST: RC0402_25,RC0402_HD,0402_CC; HEIGHT: 0.55 MM; MFG_NAME01: YAGEO AMERICA; MFG_PN01: RC0402JR-074K7L; ROHS: Yes; SIGNAL_MODEL: DEFAULT_RESISTOR_4700OHM_2_1; TOL: 1%; Tolerance: 5%
R6 R21 R32 R42 R43 = RES: RES MF 10.0K 1/16W 1% AEC-Q200 0402; AGILE_PN: 470-75416; CAD_APPROVED: Yes; FPLIST: RC0402_25,RC0402_HD,0402_CC; MFG_NAME01: VISHAY INTERTECHNOLOGY; MFG_PN01: CRCW040210K0FKED; PRIORITY_PN: 006-00552; ROHS: Yes; SIGNAL_MODEL: DEFAULT_RESISTOR_10000OHM_2_1; Tolerance: 1%
R7 R31 R40 = RES: RES MF 10.0K 1/16W 1% AEC-Q200 0402; AGILE_PN: 470-75416; ASSY_OPT: DNP; CAD_APPROVED: Yes; FPLIST: RC0402_25,RC0402_HD,0402_CC; MFG_NAME01: VISHAY INTERTECHNOLOGY; MFG_PN01: CRCW040210K0FKED; PRIORITY_PN: 006-00552; ROHS: Yes; SIGNAL_MODEL: DEFAULT_RESISTOR_10000OHM_2_1; Tolerance: 1%
R8 R41 R48-R50 = RES: RES MF 4.7K 1/16W 5% 0402; AGILE_PN: 470-75626; ASSY_OPT: DNP; CAD_APPROVED: Yes; FPLIST: RC0402_25,RC0402_HD,0402_CC; HEIGHT: 0.55 MM; MFG_NAME01: YAGEO AMERICA; MFG_PN01: RC0402JR-074K7L; ROHS: Yes; SIGNAL_MODEL: DEFAULT_RESISTOR_4700OHM_2_1; TOL: 1%; Tolerance: 5%
R10 = RES: RES MF ZERO OHM 1/16W 5% 0402; AGILE_PN: 470-75394; ASSY_OPT: DNP; CAD_APPROVED: Yes; FPLIST: RC0402_25,RC0402_HD,RC0402_X2,0402_CC; HEIGHT: 0.45 MM; MFG_NAME01: ROHM; MFG_PN01: MCR01MZPJ000; PRIORITY_PN: 006-00559; ROHS: Yes; SIGNAL_MODEL: DEFAULT_RESISTOR_0.001OHM_2_1; TOL: 5%; Tolerance: 5%; VOLTAGE: 1/16W
R11 = RES: RES MF 180K  1/16W 1% 0402; AGILE_PN: 470-31088; CAD_APPROVED: Yes; FPLIST: RC0402_25,RC0402_HD,0402_CC; MFG_NAME01: KOA SPEER; MFG_PN01: RK73H1ETTP1803F; ROHS: Yes; SIGNAL_MODEL: DEFAULT_RESISTOR_180000OHM_2_1; Tolerance: 1%
R13 R14 R16 R26 R27 R39 = RES: RES MF 10.0K 1/16W 1% AEC-Q200 0402; AGILE_PN: 470-75416; CAD_APPROVED: Yes; FPLIST: RC0402_25,RC0402_HD,0402_CC; HEIGHT: 0.55MM; MFG_NAME01: VISHAY INTERTECHNOLOGY; MFG_PN01: CRCW040210K0FKED; PRIORITY_PN: 006-00552; ROHS: Yes; SIGNAL_MODEL: DEFAULT_RESISTOR_10000OHM_2_1; TOL: 5%; Tolerance: 1%
R17 = RES: RES MF 220 OHM 1/10W 5% 0603; AGILE_PN: 470-30297; CAD_APPROVED: Yes; FPLIST: RC0603_OV,RC0603,0603_CC; MFG_NAME01: KOA SPEER; MFG_PN01: RK73B1JTTD221J; ROHS: Yes; SIGNAL_MODEL: DEFAULT_RESISTOR_220.000000OHM_2_1; Tolerance: 5%
R20 R22 = RES: RES MF 33.0 OHM 1/16W 1% 0402; AGILE_PN: 470-75790; CAD_APPROVED: Yes; FPLIST: RC0402_25,RC0402_HD,RC0402_X2,0402_CC; MFG_NAME01: THYE MING TECH CO LTD; MFG_PN01: CR-02FL6---33R; PRIORITY_PN: 006-00556; ROHS: Yes; SIGNAL_MODEL: DEFAULT_RESISTOR_33.000000OHM_2_1; Tolerance: 1%
R24 R38 = RES: RES MF ZERO OHM 1/16W 5% 0402; AGILE_PN: 470-75394; CAD_APPROVED: Yes; FPLIST: RC0402_25,RC0402_HD,RC0402_X2,0402_CC; HEIGHT: 0.45 MM; MFG_NAME01: ROHM; MFG_PN01: MCR01MZPJ000; PRIORITY_PN: 006-00559; ROHS: Yes; SIGNAL_MODEL: DEFAULT_RESISTOR_0.001OHM_2_1; TOL: 5%; Tolerance: 5%; VOLTAGE: 1/16W
R29 = RES: RES MF 1.0K 1/16W 1% 0402; AGILE_PN: 470-76037; CAD_APPROVED: Yes; FPLIST: RC0402_25,RC0402_HD,RC0402_X2,0402_CC; HEIGHT: 0.4MM; MFG_NAME01: YAGEO AMERICA; MFG_PN01: RC0402FR-071KL; PRIORITY_PN: 006-00553; ROHS: Yes; SIGNAL_MODEL: DEFAULT_RESISTOR_1000.000000OHM_2_1; TOL: 1%; Tolerance: 1%; VOLTAGE: 1/16W
R30 = RES: RES MF 15K  1/16W 1% 0402; AGILE_PN: 470-30965; CAD_APPROVED: Yes; FPLIST: RC0402_25,RC0402_HD,0402_CC; HEIGHT: 0.4 MM; MFG_NAME01: KOA SPEER; MFG_PN01: RK73H1ETTP1502F; ROHS: Yes; SIGNAL_MODEL: DEFAULT_RESISTOR_15000OHM_2_1; TOL: 1%; Tolerance: 1%
R34 = RES: RES MF 10.0K 1/16W 1% AEC-Q200 0402; AGILE_PN: 470-75416; ASSY_OPT: DNP; CAD_APPROVED: Yes; FPLIST: RC0402_25,RC0402_HD,0402_CC; HEIGHT: 0.4MM; MFG_NAME01: VISHAY INTERTECHNOLOGY; MFG_PN01: CRCW040210K0FKED; PRIORITY_PN: 006-00552; ROHS: Yes; SIGNAL_MODEL: DEFAULT_RESISTOR_10000OHM_2_1; TOL: 1%; Tolerance: 1%
R1 R35 R75 = RES: RES MF 10.0K 1/16W 1% AEC-Q200 0402; AGILE_PN: 470-75416; CAD_APPROVED: Yes; FPLIST: RC0402_25,RC0402_HD,0402_CC; HEIGHT: 0.4MM; MFG_NAME01: VISHAY INTERTECHNOLOGY; MFG_PN01: CRCW040210K0FKED; PRIORITY_PN: 006-00552; ROHS: Yes; SIGNAL_MODEL: DEFAULT_RESISTOR_10000OHM_2_1; TOL: 1%; Tolerance: 1%
R36 = RES: RES MF ZERO OHM 1/10W -- 0603; AGILE_PN: 470-75407; CAD_APPROVED: Yes; FPLIST: RC0603_OV,RC0603,R603-X2,0603_CC; MFG_NAME01: VISHAY INTERTECHNOLOGY; MFG_PN01: CRCW06030000Z0EA; ROHS: Yes; Tolerance: 1%
SH1 = RES_SHORT-2: ZERO OHM CUT TRACE 0603 PADS; NO PART TO ORDER; AGILE_PN: 470-80018; CAD_APPROVED: Yes; FPLIST: SH0603,SH0603_CC,SH0603-X2_PIN1TO2,SH0603-X2_PIN2TO3; MFG_NAME01: LAYOUT ELEMENT ONLY; MFG_PN01: LAYOUT ELEMENT ONLY; ROHS: Yes; SIGNAL_MODEL: DEFAULT_RESISTOR_0.001OHM_2_1
SW1-SW3 = SW2_STM151XX: SW SPST MOM NO TACT 12V 50MA SMT; AGILE_PN: 510-76958; CAD_APPROVED: Yes; HEIGHT: 2MM; MFG_NAME01: E SWITCH; MFG_PN01: TL1015BF160QG; ROHS: Yes
U1 U4 U6 = DIODE_TVS_BIDIR: DIODE TVS BIDIR -- 30V 0402; AGILE_PN: 480-76179; CAD_APPROVED: Yes; HEIGHT: 0.44MM; MFG_NAME01: COOPER BUSSMANN; MFG_PN01: 0402ESDA-MLP1; PRIORITY_PN: 048-0402ESDA; ROHS: Yes
U2 U7 U12 = 74LVCH1T45_6P: IC XCVR 1BIT 3-STATE DUAL 1.2-5.5V XSON6; AGILE_PN: 312-80758; CAD_APPROVED: Yes; HEIGHT: 0.5MM; MFG_NAME01: NXP SEMICONDUCTORS; MFG_PN01: 74LVCH1T45GM,132; ROHS: Yes; VOLTAGE: 1.2-5.5V
U3 = NTSX2102GU8H_8P: IC DUAL SUPPLY XCVR 50 MBPS 5.5V XQFN8; AGILE_PN: 312-80763; CAD_APPROVED: Yes; HEIGHT: 0.5MM; MFG_NAME01: NXP Semiconductors; ROHS: Yes; VOLTAGE: 5.5V
U5 = PK20DX128V_QFN_32P: IC MCU FLASH 128KB 50MHZ 1.71-3.6V QFN32; AGILE_PN: 344-01231; CAD_APPROVED: Yes; HEIGHT: 1MM; MFG_NAME01: FREESCALE SEMICONDUCTOR; ROHS: Yes; VOLTAGE: 1.71-3.6V
U9 = NLU2GU04: IC INV DUAL SCHMITT TRIGGER 1.65-5.5V ULLGA6; AGILE_PN: 315-78830; CAD_APPROVED: Yes; HEIGHT: 0.4MM; MFG_NAME01: On Semiconductor; MFG_PN01: NLX2G14AMUTCG; ROHS: Yes; VOLTAGE: 1.65-5.5V
U10 = 74LVC2T45GM_8P: IC XCVR DUAL SUPPLY 1.2 -5.5V XQFN8; AGILE_PN: 312-80762; CAD_APPROVED: Yes; HEIGHT: 0.5MM; MFG_NAME01: NXP Semiconductors; ROHS: Yes; VOLTAGE: 5.5V
U11 = MIC2005-0.8YM6: IC LIN SW PWR 0.8A 2.5-5.5V SOT23-6; AGILE_PN: 315-79199; CAD_APPROVED: Yes; HEIGHT: 1.45MM; MFG_NAME01: MICREL; PRIORITY_PN: 051-MIC2005-08; ROHS: Yes; VOLTAGE: 2.5-5.5V
Y1 = XTAL_CS: XTAL 8.00MHZ RSN CERAMIC -- SMT; AGILE_PN: 230-77664; CAD_APPROVED: Yes; HEIGHT: 0.8MM; MFG_NAME01: MURATA; MFG_PN01: CSTCE8M00G55-R0; PRIORITY_PN: 048-00290; ROHS: Yes
C3 C4 C13 C14 C56 = CAP_NP: CAP CER 0.1UF 10V 10% X5R 0402; AGILE_PN: 150-75634; CAD_APPROVED: Yes; FPLIST: CC0402_25,CC0402_HD,0402_CC; HEIGHT: 0.64MM; MFG_NAME01: KEMET; MFG_PN01: C0402C104K8PAC; PRIORITY_PN: 021-00169; ROHS: Yes; SIGNAL_MODEL: DEFAULT_CAPACITOR_100000pF_2_1; Tolerance: 10%; VOLTAGE: 10V
C5 = CAP_NP: CAP CER 4.7uF 16V 10% X5R 0603; AGILE_PN: 150-78976; CAD_APPROVED: Yes; FPLIST: CC0603_OV,CC0603,0603_CC; HEIGHT: 0.9 MM; MFG_NAME01: TDK; MFG_PN01: C1608X5R1C475K; ROHS: Yes; SIGNAL_MODEL: DEFAULT_CAPACITOR_4.7e+06pF_2_1; Tolerance: 10%; VOLTAGE: 16V
C41 = CAP_NP: CAP CER 10uF 16V 20% X5R 0603; AGILE_PN: 150-79092; CAD_APPROVED: Yes; FPLIST: CC0603_OV,CC0603,0603_CC; HEIGHT: 1mm; MFG_NAME01: TAIYO YUDEN; MFG_PN01: EMK107BBJ106MA-T; ROHS: Yes; SIGNAL_MODEL: DEFAULT_CAPACITOR_1e+07pF_2_1; Tolerance: 20%; VOLTAGE: 16V
C50 C52 C54 = CAP_NP: CAP CER 10uF 16V 20% X5R 0603; AGILE_PN: 150-79092; ASSY_OPT: DNP; CAD_APPROVED: Yes; FPLIST: CC0603_OV,CC0603,0603_CC; HEIGHT: 1mm; MFG_NAME01: TAIYO YUDEN; MFG_PN01: EMK107BBJ106MA-T; ROHS: Yes; SIGNAL_MODEL: DEFAULT_CAPACITOR_1e+07pF_2_1; Tolerance: 20%; VOLTAGE: 16V
C51 = CAP_NP: CAP CER 10UF 10V 20% X5R 0603; AGILE_PN: 150-78609; CAD_APPROVED: Yes; FPLIST: CC0603_OV,CC0603,0603_CC; HEIGHT: 1.016MM; MFG_NAME01: TAIYO YUDEN; MFG_PN01: LMK107BJ106MALTD; ROHS: Yes; SIGNAL_MODEL: DEFAULT_CAPACITOR_1e+07pF_2_1; VOLTAGE: 10V
C53 = CAP_NP: CAP CER 10UF 10V 20% X5R 0603; AGILE_PN: 150-78609; ASSY_OPT: DNP; CAD_APPROVED: Yes; FPLIST: CC0603_OV,CC0603,0603_CC; HEIGHT: 1.016MM; MFG_NAME01: TAIYO YUDEN; MFG_PN01: LMK107BJ106MALTD; ROHS: Yes; SIGNAL_MODEL: DEFAULT_CAPACITOR_1e+07pF_2_1; VOLTAGE: 10V
C55 = CAP_NP: CAP CER 0.1UF 10V 10% X5R 0402; AGILE_PN: 150-75634; ASSY_OPT: DNP; CAD_APPROVED: Yes; FPLIST: CC0402_25,CC0402_HD,0402_CC; HEIGHT: 0.64MM; MFG_NAME01: KEMET; MFG_PN01: C0402C104K8PAC; PRIORITY_PN: 021-00169; ROHS: Yes; SIGNAL_MODEL: DEFAULT_CAPACITOR_100000pF_2_1; Tolerance: 10%; VOLTAGE: 10V
D5 D6 D9-D11 = DIODE_SCHTKY: DIODE SCH 1A 30V PowerDI123; AGILE_PN: 480-78285; CAD_APPROVED: Yes; HEIGHT: 1MM; MFG_NAME01: DIODES INC; ROHS: Yes
D13 = DIODE_SCHTKY: DIODE SCH 1A 30V PowerDI123; AGILE_PN: 480-78285; ASSY_OPT: DNP; CAD_APPROVED: Yes; HEIGHT: 1MM; MFG_NAME01: DIODES INC; ROHS: Yes
J1 J3 = CONN_HDR_8X2: CON 2X8 SKT TH 100MIL CTR 545H SN 190L; AGILE_PN: 210-80538; CAD_APPROVED: Yes; HEIGHT: 13.843MM; MFG_NAME01: samtec; MFG_PN01: ESQ-108-23-T-D; ROHS: Yes
J2 = CONN_HDR_10X2: CON 2X10 SKT TH 100MIL CTR 540H SN 190L; AGILE_PN: 210-80537; CAD_APPROVED: Yes; HEIGHT: 13.72MM; MFG_NAME01: SAMTEC; MFG_PN01: ESQ-110-23-T-D; ROHS: Yes
J4 = CONN_HDR_6X2: CON 2X6 SKT TH 100MIL CTR 540H SN 190L; AGILE_PN: 210-80536; CAD_APPROVED: Yes; HEIGHT: 13.72MM; MFG_NAME01: SAMTEC; MFG_PN01: ESQ-106-23-T-D; ROHS: Yes
J18 = CONN_HDR_2X1: HDR 1X2 TH 100MIL SP 330H SN 115L; AGILE_PN: 210-76752; ASSY_OPT: DNP; CAD_APPROVED: Yes; HEIGHT: 8.58MM; MFG_NAME01: Samtec; MFG_PN01: TSW-102-23-T-S; ROHS: Yes
J24 = DC_POWER_JACK: CON 3 PWR JACK RA TH --- 201H AG 118L; AGILE_PN: 210-80316; ASSY_OPT: DNP; CAD_APPROVED: Yes; HEIGHT: 5.1MM; MFG_NAME01: CUI Inc; MFG_PN01: PJ1-022; ROHS: Yes
J27 = CONN_HDR_3X1: HDR 1X3 TH 100MIL SP 330H AU 98L; AGILE_PN: 210-75442; ASSY_OPT: DNP; CAD_APPROVED: Yes; HEIGHT: 8.38 MM; MFG_NAME01: SAMTEC; MFG_PN01: HTSW-103-07-S-S; PRIORITY_PN: 028-00700; ROHS: Yes
TP16 = TestLoop: TEST POINT WHITE 40 MIL DRILL 180 MIL TH 109L; AGILE_PN: 210-75685; ASSY_OPT: DNP; CAD_APPROVED: Yes; HEIGHT: 4.8 MM; MFG_NAME01: KEYSTONE ELECTRONICS; MFG_PN01: 5002; PRIORITY_PN: 028-00434; ROHS: Yes
U8 = FXOS8700CQ_QFN_16P: IC ACCELEROMETER AND MAGNETOMETER SENSOR 3-AXIS 2.5V QFN16; AGILE_PN: TMP-WF-16648; CAD_APPROVED: Yes; HEIGHT: 1.25MM; MFG_NAME01: Freescale Semiconductor; PRE_APN: 312-80418; ROHS: Yes; VOLTAGE: 2.5V
U17 = LD1117AS18: IC VREG LDO 1A 3.3V SOT223; AGILE_PN: 312-80039; CAD_APPROVED: Yes; HEIGHT: 1.8MM; MFG_NAME01: ON Semiconductor; ROHS: Yes

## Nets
GND: C1.2 C2.2 C3.2 C4.2 C5.2 C6.2 C7.2 C8.2 C9.2 C10.2 C11.2 C12.2 C13.2 C14.2 C15.2 C16.2 C17.2 C18.2 C22.2 C23.2 C24.2 C25.2 C26.2 C27.2 C28.2 C29.2 C30.2 C32.2 C35.2 C37.1 C38.1 C40.2 C41.2 C43.2 C44.2 C50.2 C51.2 C52.2 C53.2 C54.2 C55.2 C56.2 C505.2 C507.2 C516.2 C522.2 D7.A(ANODE) J2.14 J3.12(B6) J3.14(B7) J6.5(P5) J9.3(A2) J9.5(A3) J10.3(A2) J10.5(A3) J24.2 J24.3 J27.2 L1.2 R6.2 R7.2 R13.2 R16.2 R30.2 R31.2 R39.2 R42.2 R43.2 R44.2 R60.2 R62.1 SW1.1(SW1) SW2.2(SW2) SW3.2(SW2) TP16.1(Pin1) TP21.1(Pin1) TP22.1(Pin1) TP23.1(Pin1) TP24.1(Pin1) U1.2(A2) U2.2(GND) U3.4(GND) U4.2(A2) U5.2(VSS1) U5.8(VSSA) U5.33(EPAD) U6.2(A2) U7.2(GND) U8.3(RSVD1) U8.5(GND1) U8.12(GND2) U8.13(RSVD2) U9.2(GND) U10.3(DIR) U10.4(GND) U11.2(GND) U12.2(GND) U13.9(VSS1) U13.29(VSS2) U13.41(VSS3) U13.49(VSS4) U13.60(VSS5) U13.74(VSS6) U13.88(VSS7) U17.1(GND) X501.2 Y1.2
P3V3: C4.1 C5.1 C14.1 C40.1 D11.C J3.4(B2) J3.8(B4) J18.2 J19.1 J20.1 R1.1 R9.1 R15.1 R32.1 R40.1 R41.1 R45.1 R48.1 R49.1 R50.1 R61.1 R63.1 R75.1 R88.1 SH1.2 U8.1(VDDIO) U8.14(VDD)
P3V3_KV31: C24.1 C25.1 C26.1 C27.1 C28.1 C29.1 C30.1 C32.1 J9.1(A1) J20.2 R63.2 R66.1 R68.1 TP37.1(Pin1) U13.8(VDD1) U13.22(VDDA) U13.30(VDD2) U13.40(VDD3) U13.48(VDD4) U13.61(VDD5) U13.75(VDD6) U13.89(VDD7)
P3V3_SDA: C8.1 C10.1 C12.1 C15.1 C17.1 C18.1 J10.1(A1) J18.1 R4.2 R12.1 R14.1 R17.1 R21.1 R23.1 R26.1 R27.2 R35.1 R36.1 R37.1 R61.2 TP38.1(Pin1) U2.1(VCCA) U3.1(VCCA) U5.1(VDD1) U5.7(VDDA) U5.11(VBAT) U7.1(VCCA) U9.5(VCC) U10.7(VCCA) U12.1(VCCA)
P3V3_VREG: C51.1 D11.A J19.2 TP56.1(Pin1) U17.2(VOUT) U17.4(TAB)
P5V0_SDA_USB_CONN_VBUS: J6.1(P1) L2.1 U1.1(A1)
P5V_OPT_VR: C53.1 D13.A J27.3
P5V_SDA: C1.1 C16.1 C19.1 L2.2 R5.1 R8.1 R34.1 TP12.1(Pin1) U5.6(VREGIN) U11.1(VIN)
P5V_SDA_PSW: D5.A D6.A TP19.1(Pin1) U11.6(VOUT)
P5V_USB: D5.C D13.C J3.10(B5)
VSSA: R60.1 U13.25(VSSA)
8MHz_EXTAL: C37.2 R52.1 TP35.1(Pin1) U13.50(PTA18/EXTAL0/FTM0_FLT2/FTM_CLKIN0) X501.1
ADC0_DM0: J4.5(A3) U13.19(ADC0_DM0/ADC1_DM3)
ADC0_DM1: J4.3(A2) U13.15(ADC0_DM1)
ADC0_DP0: C44.1 R76.1 U13.18(ADC0_DP0/ADC1_DP3)
ADC0_DP0_RC: J2.5 R76.2
ADC0_DP1: J4.1(A1) U13.14(ADC0_DP1)
ADC1_DM0: J4.7(A4) U13.21(ADC1_DM0/ADC0_DM3)
ADC1_DM1: C35.1 R46.1 U13.17(ADC1_DM1/ADC0_DM2)
ADC1_DP0: C507.1 R551.1 U13.20(ADC1_DP0/ADC0_DP3)
ADC1_DP0_RC: J2.3 R551.2
ADC1_DP1: C22.1 R47.1 U13.16(ADC1_DP1/ADC0_DP2)
ADC1_SE18: C505.1 R534.1 U13.26(VREF_OUT/CMP1_IN5/CMP0_IN5/ADC1_SE18)
ADC1_SE18_RC: J2.9 R534.2
ADC1_SE23: J2.11 U13.28(DAC1_OUT/CMP0_IN4/ADC1_SE23)
AREF: J2.16 R53.2
DAC0_OUT: C43.1 J4.11(A6) U13.27(DAC0_OUT/CMP1_IN3/ADC0_SE23)
DC_JACK: D9.A J24.1(Pin)
FXOS8700CQ_CRST: C13.1 U8.8(CRST)
FXOS8700CQ_I2C_SA0: R31.1 R32.2 TP8.1(Pin1) U8.7(SA0/MISO)
FXOS8700CQ_I2C_SA1: R40.2 R43.1 TP11.1(Pin1) U8.10(SA1/~{CS})
I2C0_SCL_PKYK: R56.1 U13.95(PTD2/LLWU_P13/SPI0_SOUT/UART2_RX/FTM3_CH2/FBA_AD4/LPUART0_RX/I2C0_SCL)
I2C0_SDA_PKYK: R57.2 U13.96(PTD3/SPI0_SIN/UART2_TX/FTM3_CH3/FBA_AD3/LPUART0_TX/I2C0_SDA)
JTAG_TDI: U13.35(PTA1/UART0_RX/FTM0_CH6/CMP0_OUT/FTM2_QD_PHA/FTM1_CH1/JTAG_TDI/EZP_DI)
LEDRGB_BLUE: D4.3(BLUE_C) R73.1 TP14.1(Pin1)
LEDRGB_GREEN: D4.4(GREEN_C) R74.1 TP17.1(Pin1)
LEDRGB_RED: D4.1(RED_C) R69.2 TP13.1(Pin1)
LVLRST_EN: R4.1 U3.5(OE)
MIC2005_CSLEW: C19.2 U11.5(CSLEW)
MMA8451_BYP: C3.1 TP4.1(Pin1) U8.2(BYP)
P5-9V_VIN: C50.1 C52.1 C54.1 D10.A J3.16(B8) J27.1 TP20.1(Pin1)
P5-9V_VIN_VR: C41.1 D6.C D9.C D10.C U17.3(VIN)
POWER_EN: R29.1 U5.31(ADC0_SE7B/PTD6/SPI0_PCS3/UART0_RX/FTM0_CH6/FTM0_FLT0/LLWU_P15)
PTA2: R80.2 TP32.1(Pin1) U13.36(PTA2/UART0_TX/FTM0_CH7/CMP1_OUT/FTM2_QD_PHB/FTM1_CH0/JTAG_TDO/TRACE_SWO/EZP_DO)
PTA4: C56.1 R1.2 SW2.1(SW1) U13.38(PTA4/LLWU_P3/FTM0_CH1/FTM0_FLT3/~{NMI}/~{EZP_CS})
PTA5: J2.4 U13.39(PTA5/FTM0_CH2/~{JTAG_TRST})
PTA12: J1.12(B6) U13.42(PTA12/FTM1_CH0/FTM1_QD_PHA)
PTA13: J1.3(A2) U13.43(PTA13/LLWU_P4/FTM1_CH1/FTM1_QD_PHB)
PTA17: J2.15 U13.47(PTA17/ADC1_SE17/SPI0_SIN/~{UART0_RTS})
PTB0: C522.1 R555.1 U13.53(PTB0/LLWU_P5/ADC0_SE8/ADC1_SE8/I2C0_SCL/FTM1_CH0/FTM1_QD_PHA/UART0_RX)
PTB0_RC: J2.1 R555.2
PTB1: J2.18 R48.2 U13.54(PTB1/ADC0_SE9/ADC1_SE9/I2C0_SDA/FTM1_CH1/FTM0_FLT2/EWM_IN/FTM1_QD_PHB/UART0_TX)
PTB2: J2.20 R41.2 U13.55(PTB2/ADC0_SE12/I2C0_SCL/~{UART0_RTS}/FTM0_FLT1/FTM0_FLT3)
PTB3: C516.1 R549.1 U13.56(PTB3/ADC0_SE13/I2C0_SDA/~{UART0_CTS}/FTM0_FLT0)
PTB3_RC: J2.7 R549.2
PTB10: J2.19 U13.58(PTB10/ADC1_SE14/SPI1_PCS0/LPUART0_RX/FBA_AD19/FTM0_FLT1)
PTB11: J4.6(B3) U13.59(PTB11/ADC1_SE15/SPI1_SCK/LPUART0_TX/FBA_AD18/FTM0_FLT2)
PTB18: J3.3(A2) U13.64(PTB18/FTM2_CH0/FBA_AD15/FTM2_QD_PHA)
PTB19: J3.1(A1) U13.65(PTB19/FTM2_CH1/~{FBA_OE}/FTM2_QD_PHB)
PTB20: J2.17 U13.66(PTB20/FBA_AD31/CMP0_OUT)
PTB21: J4.9(A5) U13.67(PTB21/FBA_AD30/CMP1_OUT)
PTB22: R64.2 U13.68(PTB22/FBA_AD29)
PTC0: J4.8(B4) U13.70(PTC0/ADC0_SE14/SPI0_PCS4/PDB0_EXTRG/FBA_AD14/FTM0_FLT1/SPI0_PCS0)
PTC1: J3.15(A8) U13.71(PTC1/LLWU_P6/ADC0_SE15/SPI0_PCS3/~{UART1_RTS}/FTM0_CH0/FBA_AD13/~{LPUART0_RTS})
PTC2: J3.13(A7) U13.72(PTC2/ADC0_SE4B/CMP1_IN0/SPI0_PCS2/~{UART1_CTS}/FTM0_CH1/FBA_AD12/~{LPUART0_CTS})
PTC3: J1.14(B7) U13.73(PTC3/LLWU_P7/CMP1_IN1/SPI0_PCS1/UART1_RX/FTM0_CH2/CLKOUT/LPUART0_RX)
PTC4: J3.9(A5) U13.76(PTC4/LLWU_P8/SPI0_PCS0/UART1_TX/FTM0_CH3/FBA_AD11/CMP1_OUT/LPUART0_TX)
PTC5: J3.11(A6) U13.77(PTC5/LLWU_P9/SPI0_SCK/LPTMR0_ALT2/FBA_AD10/CMP0_OUT/FTM0_CH2)
PTC6: J1.16(B8) U13.78(PTC6/LLWU_P10/CMP0_IN0/SPI0_SOUT/PDB0_EXTRG/FBA_AD9/I2C0_SCL)
PTC7: J2.13 U13.79(PTC7/CMP0_IN1/SPI0_SIN/FBA_AD8/I2C0_SDA)
PTC8: J4.2(B1) U13.80(PTC8/ADC1_SE4B/CMP0_IN2/FTM3_CH4/FBA_AD7)
PTC9: J4.4(B2) U13.81(PTC9/ADC1_SE5B/CMP0_IN3/FTM3_CH5/FBA_AD6/FTM2_FLT0)
PTC10: J4.12(B6) R50.2 U13.82(PTC10/ADC1_SE6B/I2C1_SCL/FTM3_CH6/FBA_AD5)
PTC11: J4.10(B5) R49.2 U13.83(PTC11/LLWU_P11/ADC1_SE7B/I2C1_SDA/FTM3_CH7/~{FBA_RW})
PTC12: J1.1(A1) U13.84(PTC12/FBA_AD27/FTM3_FLT0)
PTC13: J1.10(B5) U13.85(PTC13/FBA_AD26)
PTC15: J1.5(A3) U13.87(PTC15/FBA_AD24)
PTC16: J1.7(A4) U13.90(PTC16/LPUART0_RX/~{FBA_CS5}/FBA_TSIZ1/~{FBA_BE23_16_BLS15_8})
PTC17: J1.9(A5) U13.91(PTC17/LPUART0_TX/~{FBA_CS4}/FBA_TSIZ0/~{FBA_BE31_24_BLS7_0})
PTC18: U8.9(INT2) U13.92(PTC18/~{LPUART0_RTS}/~{FBA_TBST}/~{FBA_CS2}/~{FBA_BE15_8_BLS23_16})
PTD0: U8.11(INT1) U13.93(PTD0/LLWU_P12/SPI0_PCS0/~{UART2_RTS}/FTM3_CH0/FBA_ALE/~{FBA_CS1}/~{FBA_TS}/~{LPUART0_RTS})
PTD1: R69.1 U13.94(PTD1/ADC0_SE5B/SPI0_SCK/~{UART2_CTS}/FTM3_CH1/~{FBA_CS0}/~{LPUART0_CTS})
PTD2: R9.2 R56.2 U8.4(SCL/SCLK)
PTD3: R15.2 R57.1 U8.6(SDA/MOSI)
PTD4: J3.7(A4) U13.97(PTD4/LLWU_P14/SPI0_PCS1/~{UART0_RTS}/FTM0_CH4/FBA_AD2/EWM_IN/SPI1_PCS0)
PTD5: J3.5(A3) U13.98(PTD5/ADC0_SE6B/SPI0_PCS2/~{UART0_CTS}/FTM0_CH5/FBA_AD1/~{EWM_OUT}/SPI1_SCK)
PTD6: J2.6 U13.99(PTD6/LLWU_P15/ADC0_SE7B/SPI0_PCS3/UART0_RX/FTM0_CH6/FBA_AD0/FTM0_FLT0/SPI1_SOUT)
PTD7: R74.2 U13.100(PTD7/UART0_TX/FTM0_CH7/FTM0_FLT1/SPI1_SIN)
PTE0: J1.4(B2) R58.2
PTE1: J1.2(B1) R59.1
PTE2: J1.11(A6) U13.3(PTE2/LLWU_P1/ADC1_SE6A/SPI1_SCK/~{UART1_CTS})
PTE3: J1.13(A7) U13.4(PTE3/ADC1_SE7A/SPI1_SIN/~{UART1_RTS}/SPI1_SOUT)
PTE4: C55.1 R67.2 R75.2 SW3.1(SW1)
PTE5: J1.6(B3) R65.1
PTE6: J1.8(B4) U13.7(PTE6/SPI1_PCS3/~{LPUART0_CTS}/FTM3_CH1)
PTE16: J1.15(A8) U13.10(PTE16/ADC0_SE4A/SPI0_PCS0/UART2_TX/FTM_CLKIN0/FTM0_FLT3)
PTE17: J2.12 U13.11(PTE17/ADC0_SE5A/SPI0_SCK/UART2_RX/FTM_CLKIN1/LPTMR0_ALT3)
PTE18: J2.8 U13.12(PTE18/ADC0_SE6A/SPI0_SOUT/~{UART2_CTS}/I2C0_SDA)
PTE19: J2.10 U13.13(PTE19/ADC0_SE7A/SPI0_SIN/~{UART2_RTS}/I2C0_SCL)
PTE24: J2.2 U13.31(PTE24/ADC0_SE17/FTM0_CH0/I2C0_SCL/~{EWM_OUT})
PTE25: R73.2 U13.32(PTE25/ADC0_SE18/FTM0_CH1/I2C0_SDA/EWM_IN)
RST_TGTMCU_B: D1.C(CATHODE) J3.6(B3) J9.10(B5) J25.3 R10.2 R11.2 TP33.1(Pin1) U3.7(B1) U13.52(~{RESET})
SDA_EXTAL: C9.1 U5.17(EXTAL0/PTA18/FTM0_FLT2/FTM_CLKIN0) Y1.3
SDA_JTAG_TCLK: J10.4(B2) TP26.1(Pin1) U5.12(JTAG_TCLK/SWD_CLK/EZP_CLK/TSI0_CH1/PTA0/~{UART0_CTS}/~{UART0_COL}/FTM0_CH5)
SDA_JTAG_TDI: J10.8(B4) TP28.1(Pin1) U5.13(JTAG_TDI/EZP_DI/TSI0_CH2/PTA1/UART0_RX/FTM0_CH6)
SDA_JTAG_TDO: J10.6(B3) TP27.1(Pin1) U5.14(JTAG_TDO/TRACE_SWO/EZP_DO/TSI0_CH3/PTA2/UART0_TX/FTM0_CH7)
SDA_JTAG_TMS: J10.2(B1) R21.2 TP25.1(Pin1) U5.15(JTAG_TMS/SWD_DIO/TSI0_CH4/PTA3/~{UART0_RTS}/FTM0_CH0)
SDA_LED: D2.C(CATHODE) U5.29(PTD4/SPI0_PCS1/~{UART0_RTS}/FTM0_CH4/EWM_IN/LLWU_P14)
SDA_LED_R: D2.A(ANODE) R17.2
SDA_RST: J10.10(B5) R5.2 R6.1 TP5.1(Pin1) TP29.1(Pin1) U5.19(~{RESET})
SDA_RST_LED: D1.A(ANODE) R2.2
SDA_RST_TGTMCU_B: J5.2 U5.21(ADC0_SE9/TSI0_CH6/PTB1/I2C0_SDA/FTM1_CH1/FTM1_QD_PHB)
SDA_RST_TGTMCU_J_B: J5.1 J25.1 R10.1 R14.2 U3.2(A1)
SDA_RX_EN: R16.1 R23.2 U7.5(DIR)
SDA_SPI0_CS: R3.2 TP1.1(Pin1) U5.23(ADC0_SE4B/CMP1_IN0/TSI0_CH15/PTC2/SPI0_PCS2/~{UART1_CTS}/FTM0_CH1/I2S0_TX_FS)
SDA_SPI0_RST_B: R18.2 TP6.1(Pin1) U5.22(ADC0_SE15/TSI0_CH14/PTC1/SPI0_PCS3/~{UART1_RTS}/FTM0_CH0/I2S0_TXD0/LLWU_P6)
SDA_SPI0_SCK: U2.3(A) U5.26(PTC5/SPI0_SCK/LPTMR0_ALT2/I2S0_RXD0/CMP0_OUT/LLWU_P9)
SDA_SPI0_SIN: U5.28(CMP0_IN1/PTC7/SPI0_SIN/USB_SOF_OUT/I2S0_RX_FS) U10.5(2A)
SDA_SPI0_SOUT: U5.27(CMP0_IN0/PTC6/SPI0_SOUT/PDB0_EXTRG/I2S0_RX_BCLK/I2S0_MCLK/LLWU_P10) U12.3(A)
SDA_SWD_EN: R18.1 R19.1 U9.6(~{Y2})
SDA_SWD_EN_B: R25.2 TP52.1(Pin1) U5.16(~{NMI}/~{EZP_CS}/TSI0_CH5/PTA4/FTM0_CH1/LLWU_P3)
SDA_SWD_EN_B_R: R25.1 R26.2 U9.1(A1)
SDA_SWD_EN_R: R12.2 R13.1 R19.2 U2.5(DIR)
SDA_SWD_OE: R3.1 R33.1 U9.4(~{Y1})
SDA_SWD_OE_B: R28.2 TP50.1(Pin1) U5.20(ADC0_SE8/TSI0_CH0/PTB0/I2C0_SCL/FTM1_CH0/FTM1_QD_PHA/LLWU_P5)
SDA_SWD_OE_B_R: R27.1 R28.1 U9.3(A2)
SDA_SWD_OE_R: R33.2 R37.2 R39.1 U12.5(DIR)
SDA_USB_CONN_DN: J6.2(P2) R22.1 U4.1(A1)
SDA_USB_CONN_DP: J6.3(P3) R20.1 U6.1(A1)
SDA_USB_DN: R22.2 U5.4(USB0_DM)
SDA_USB_DP: R20.2 U5.3(USB0_DP)
SDA_USB_P5V_SENSE: R7.1 R8.2 U5.30(ADC0_SE6B/PTD5/SPI0_PCS2/~{UART0_CTS}/~{UART0_COL}/FTM0_CH5/~{EWM_OUT})
SDA_USBSHIELD: J6.S1(SHLD1) J6.S2(SHLD2) J6.S3(SHLD3) J6.S4(SHLD4) L1.1
SDA_VOUT33: C11.1 R36.2 TP15.1(Pin1) U5.5(VOUT33)
SDA_XTAL: C6.1 U5.18(XTAL0/PTA19/FTM1_FLT0/FTM_CLKIN1/LPTMR0_ALT1) Y1.1
SW1_RST_B: C2.1 J25.2 SW1.2(SW2)
SWD_CLK_KV3x: J11.1 U13.34(PTA0/~{UART0_CTS}/FTM0_CH5/EWM_IN/JTAG_TCLK/SWD_CLK/EZP_CLK)
SWD_CLK_TGTMCU: J8.2 J9.4(B2) J11.2 TP31.1(Pin1) TP42.1(Pin1)
SWD_CLK_TGTMCU_BUF: J8.1 U2.4(B)
SWD_DIO_TGTMCU: J9.2(B1) J12.2 TP30.1(Pin1) TP41.1(Pin1) U13.37(PTA3/~{UART0_RTS}/FTM0_CH0/FTM2_FLT0/~{EWM_OUT}/JTAG_TMS/SWD_DIO)
SWD_DIO_TGTMCU_BUF: J12.1 U10.2(2B) U12.4(B)
TC_EXTAL_TP: TP9.1(Pin1) U5.10(EXTAL32)
TC_SDA_USB_ID_TP: J6.4(P4) TP7.1(Pin1)
TC_XTAL_TP: TP10.1(Pin1) U5.9(XTAL32)
THER_A: C21.1 R45.2 R47.2 RT1.1
THER_B: C21.2 R44.1 R46.2 RT1.2
TP_2102_A: TP3.1(Pin1) U3.3(A2)
TP_2102_B: TP2.1(Pin1) U3.6(B2)
TRACE_SWO: J9.6(B3) R80.1
UART0_RX_TGTMCU: R24.2 R54.2 TP39.1(Pin1)
UART0_TX_TGTMCU: R38.2 R55.1 TP40.1(Pin1)
UART1_RX_PKYK: R59.2 U13.2(PTE1/LLWU_P0/ADC1_SE5A/SPI1_SOUT/UART1_RX/I2C1_SCL/SPI1_SIN)
UART1_RX_TGTMCU_BUF: R24.1 U7.4(B)
UART1_RX_TGTMCU_R: TP49.1(Pin1) U5.25(PTC4/SPI0_PCS0/UART1_TX/FTM0_CH3/CMP1_OUT/LLWU_P8) U7.3(A)
UART1_TX_PKYK: R58.1 U13.1(PTE0/CLKOUT32K/ADC1_SE4A/SPI1_PCS1/UART1_TX/I2C1_SDA)
UART1_TX_TGTMCU_BUF: R38.1 U10.1(1B)
UART1_TX_TGTMCU_R: TP48.1(Pin1) U5.24(CMP1_IN1/PTC3/SPI0_PCS1/UART1_RX/FTM0_CH2/I2S0_TX_BCLK/LLWU_P7) U10.6(1A)
V_TGTMCU: C7.1 C23.1 R2.1 R11.1 SH1.1 TP44.1(Pin1) U2.6(VCCB) U3.8(VCCB) U7.6(VCCB) U10.8(VCCB) U12.6(VCCB)
VREFH: C33.1 C34.1 D7.C(CATHODE) R53.1 R66.2 R68.2 U13.23(VREFH)
VREFL: C33.2 C34.2 R62.2 U13.24(VREFL)
VTRG_EN: R29.2 R30.1 R34.2 U11.3(ENABLE)
VTRG_FAULT_B: R35.2 U5.32(PTD7/CMT_IRO/UART0_TX/FTM0_CH7/FTM0_FLT1) U11.4(~{FAULT})
XTAL0: C38.2 R52.2 TP36.1(Pin1) U13.51(PTA19/XTAL0/FTM0_FLT0/FTM1_FLT0/FTM_CLKIN1/LPTMR0_ALT1) X501.3
N20314503: R42.1 R64.1 U8.16(RST)
N20919516: R54.1 U13.62(PTB16/SPI1_SOUT/UART0_RX/FTM_CLKIN0/FBA_AD17/EWM_IN)
N20919519: R55.2 U13.63(PTB17/SPI1_SIN/UART0_TX/FTM_CLKIN1/FBA_AD16/~{EWM_OUT})
N20920203: R65.2 U13.6(PTE5/SPI1_PCS2/LPUART0_RX/FTM3_CH0)
N20920206: R67.1 U13.5(PTE4/LLWU_P2/SPI1_PCS0/LPUART0_TX)
N20923344: D4.2(COMMON_A) R88.2 TP43.1(Pin1)
N21097088: TP18.1(Pin1) U13.33(PTE26/CLKOUT32K)

Not connected (* = marked no-connect by the designer): J3 2(B1)*; J9 7(A4)* 8(B4)* 9(A5)*; J10 7(A4)* 9(A5)*; U8 15(NC)*; U13 44(PTA14/SPI0_PCS0/UART0_TX)* 45(PTA15/SPI0_SCK/UART0_RX)* 46(PTA16/SPI0_SOUT/~{UART0_CTS})* 57(PTB9/SPI1_PCS1/~{LPUART0_CTS}/FBA_AD20)* 69(PTB23/SPI0_PCS5/FBA_AD28)* 86(PTC14/FBA_AD25)*

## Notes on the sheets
sheet 1
- Table of Contents
- Revisions & Change Log
- 1
- TITLE PAGE
- 2
- BLOCK DIAGRAM
- Rev
- Description
- Date
- Approved
- 3
- KV31 MCU
- X1
- Initial Draft
- Jan 27
- Mario Guardado
- 4
- OpenSDA INTERFACE
- 5
- ARDUINO SHIELDS
- FREEDOM KV31F
sheet 2
- 1. Unless Otherwise Specified:
- All resistors are in ohms, most are 1%, 1/10 Watt.  Otherwise are 5%, 1/8 Watt.
- All capacitors are in uF, some are 10% or 20%
- All voltages are DC
- All polarized capacitors are tantalum
- 2. Interrupted lines coded with the same letter or letter
      combinations are electrically connected.
- 3. Device type number is for reference only. The number
      varies with the manufacturer.
- 4. Special signal usage:
- _B Denotes - Active-Low Signal
- <> or [] Denotes - Vectored Signals
- 5. Interpret diagram in accordance with American
  National Standards Institute specifications, current
  revision, with the exception of logic block symbology.
sheet 3
- KV31 - 100LQFP
- NET NAMES
- PIN FUNCTIONS USED
- PIN FUNCTIONS USED
- NET NAMES
- SERIAL RX/TX
  POKA-YOKE:
  Place both
  resistors
  with the same orientation
  and provide same airgap
  between RX to TX resistors
  terminals in a square fashion.
- TX
- TX
- RX
- RX
- SERIAL RX/TX
  POKA-YOKE:
  Place both
  resistors
  with the same orientation
  and provide same airgap
  between RX to TX resistors
  terminals in a square fashion.
- TX
- TX
- RX
- RX
- SWD CONNECTOR
- SHORTING HEADER ON BOTTOM LAYER
  Jumper is shorted by a cut-trace
  on bottom layer. Cutting the trace
  will effectively isolate the on-board
  MCU from the OpenSDA
  debug interface.
- 90C to -20C
- Vdiff ~ 0.372V to 2.879V
  (Ta=25C 1.650V)
- THERMISTOR
- R
- G
- B
- LED FEATURE
- RC Filter
sheet 4
- OpenSDA Interface
- RESET
- 1-2: Default.
  2-3: Reset signal direct to the MCU,
  to use when OpenSDA is not powered.
- RST Push Button
  Bypass
- TARGET MCU
  INTERFACE
  SIGNALS
- Output to system
  from Level shifter
- UART1_RX_TGTMCU
- Output to system
  from Level shifter
- Isolation
  Resistors
- UART1_TX_TGTMCU
- PU/PD LOGIC:
  SERIAL INTERFACE
  IS ALWAYS RESET
  WHEN USB PORT
  IS DISCONNECTED
- Output to system
  from Level shifter
- SWD_DIO_TGTMCU
- OPEN SDA
  POWER OUTPUTS
- HW Designer: Rafael del Rey
- OPEN SDA
  INPUT POWER
- i
- path
- i
- path
- Note: You can power openSDA
  with your own power supplies
  by replacing this rail
  (SDA_VOUT33)
  with your 3.3V power supply rail
- 3.3VDC, 10mA should be provided
  to this rail (P3V3_SDA)
  in order to power openSDA
  module
- OpenSDA INTERFACE JTAG CONNECTOR
- PWR SWITCH
- (To enable 5v from
  USB connector)
- Isolation and level shift stage
  (for 1.8 to 5V compatibility)
- PU/PD LOGIC (DIR PIN):
  BUFFER IS TRISTATED WHEN
  P3V3_SDA IS UNPOWERED
- i
- path
- SDA_VOUT33 can provide up to 120mA
  of power at 3.3VDC to your system
  P5V_TRG_SDA can provide up to 450mA
  (per USB spec) of power at 5VDC
  to your system
- ACTIVE HIGH
- I/O POWER
  INPUT
- i
- path
- V_BRD is supported
  from 1.8V to 5V
- Power should be provided
  to this rail for the logic
  related to your platform I/O
- {For enablement purposes only}
sheet 5
- I2C INERTIAL SENSOR
- ( ACCELEROMETER AND MAGNETOMETER )
- POWER
- SHORTING HEADER
  ON BOTTOM LAYER
- 20mOhm Resistor
  in layout
- SHORTING HEADER
  ON BOTTOM LAYER
- ARDUINO COMPATIBLE HEADERS
- Default I2C Slave Address:
        0011101 (0x1D)
- SAMTEC
  ESQ-110-23-T-D
- SAMTEC
  ESQ-108-23-T-D
- INTERRUPTS
- DIFF_ADC0_DM
- DIFF_ADC0_DP
- CAD NOTE:
  For routing Feasibility
- We can swap between the
  Diff pairs ADC0* & ADC1*
- 5VDC VR
  SUPPORT
- SAMTEC
  ESQ-108-23-T-D
- IN
- OUT
- DEBUG GROUND HOOK
- SAMTEC
  ESQ-106-23-T-D
- IF YOUR 5V LDO
  HAS BACKFEED PROTECTION
  JUST SHUNT
  THIS DIODE FOOTPRINT
